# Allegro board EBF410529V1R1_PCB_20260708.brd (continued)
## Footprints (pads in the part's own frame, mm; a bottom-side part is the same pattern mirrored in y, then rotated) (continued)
USB-C-SMD_TYC-324G
  oval 1.5x1 hole 1.2x0.5: (-4.06,1.45) (4.06,1.45)
  round 0.5 hole 0.5 unplated: (-3.4,0.57) (3.4,0.57)
  oval 1x2.2 hole 0.6x1.6: 1(-4.32,1.93) 4(4.32,1.93)
  oval 1.2x2.4 hole 0.6x1.9: 2(-4.32,-2.62) 3(4.32,-2.62)
  rect 0.3x1 smd: A1(-2.62,2.62) A2(-2.13,2.62) A3(-1.63,2.62) A4(-1.13,2.62) A5(-0.62,2.62) A6(-0.12,2.62) A7(0.38,2.62) A8(0.88,2.62) A9(1.37,2.62) A10(1.87,2.62) A11(2.37,2.62) A12(2.88,2.62) B1(2.63,1.28) B2(2.13,1.28) B3(1.63,1.28) B4(1.13,1.28) B5(0.62,1.28) B6(0.12,1.28) B7(-0.38,1.28) B8(-0.87,1.28) B9(-1.37,1.28) B10(-1.87,1.28) B11(-2.37,1.28) B12(-2.88,1.28)
USON_10
  rect 0.2x0.7 smd: 1(-1,-0.45) 2(-0.5,-0.45) 4(0.5,-0.45) 5(1,-0.45) 6(1,0.45) 7(0.5,0.45) 9(-0.5,0.45) 10(-1,0.45)
  rect 0.4x0.7 smd: 3(0,-0.45) 8(0,0.45)
WQFN14-0R50-2R5X2R5EP1R45X1R45
  rect 0.6x0.3 smd: 1(-1.21,0.5) 2(-1.21,0) 3(-1.21,-0.5) 8(1.21,-0.5) 9(1.21,0) 10(1.21,0.5)
  rect 0.3x0.6 smd: 4(-0.75,-1.21) 5(-0.25,-1.21) 6(0.25,-1.21) 7(0.75,-1.21) 11(0.75,1.21) 12(0.25,1.21) 13(-0.25,1.21) 14(-0.75,1.21)
  rect 1.2x1.2 smd: 15(0,0)
ZH1P5MM_TH_2P
  round 1.05 hole 0.65: 1(-0.75,0) 2(0.75,0)

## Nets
3V3_OUT: C183.1 C185.1 J23.5 U31.1(OUT)
3V3_WLAN: C141.1 C142.1 Q11.3 U22.8
5V_OUT: C186.1 C187.1 J23.3 U32.1(OUT)
12V: C3.1 C4.1 C5.1 C6.1 C7.1 C12.1 C15.1 C162.1 C163.1 C180.1 F1.2 Q15.3 R8.2 R192.1 R219.1 R221.1 U1.3(VIN) U2.3(VIN) U26.3(VIN)
12V_OUT: C181.1 C182.1 J23.1 Q16.3
GND: C3.2 C4.2 C5.2 C6.2 C7.2 C8.2 C9.2 C12.2 C13.2 C14.2 C15.2 C16.2 C17.2 C18.2 C19.2 C20.2 C21.2 C22.2 C23.2 C24.2 C25.2 C26.2 C27.2 C28.2 C29.2 C30.2 C31.2 C32.2 C33.2 C34.2 C35.2 C36.2 C37.2 C38.2 C39.2 C40.2 C41.2 C42.2 C43.2 C44.2 C45.2 C46.2 C47.2 C48.2 C49.2 C50.2 C51.2 C52.2 C53.2 C54.2 C55.2 C56.2 C57.2 C58.2 C59.2 C60.2 C61.2 C62.2 C63.2 C64.2 C65.2 C66.2 C67.2 C68.2 C69.2 C70.2 C72.2 C73.2 C77.2 C78.2 C79.2 C80.2 C83.2 C84.2 C85.2 C87.1 C88.2 C90.2 C91.2 C92.2 C93.2 C94.2 C95.2 C96.2 C103.2 C104.2 C107.2 C108.2 C109.2 C110.2 C111.2 C112.2 C113.2 C114.2 C115.2 C116.2 C117.2 C118.2 C119.2 C120.2 C121.2 C122.2 C123.2 C124.2 C125.2 C126.2 C127.2 C128.2 C129.2 C130.2 C131.2 C132.2 C133.2 C134.2 C135.2 C136.2 C137.2 C138.2 C139.2 C141.2 C142.2 C144.2 C145.2 C146.2 C147.2 C148.2 C149.2 C150.2 C151.2 C152.2 C153.2 C154.2 C155.2 C156.2 C157.2 C158.2 C159.2 C160.2 C162.2 C163.2 C165.2 C166.2 C167.2 C168.2 C169.2 C172.2 C173.2 C174.2 C175.2 C176.2 C177.2 C181.2 C182.2 C183.2 C184.2 C185.2 C186.2 C187.2 C188.2 C189.2 C190.2 C191.2 C194.2 C195.2 C196.2 C197.2 C198.2 C199.2 C200.2 C201.2 C202.2 C203.2 C204.2 C205.2 C206.2 C207.2 C208.2 C209.2 C210.2 C212.1 C213.2 C214.2 C215.2 C226.2 CN1.2 CN1.3 D1.2 D2.1 D3.1 D4.1 D5.1 D6.1 D7.1 D8.1 D10.1 D11.1 D12.1 D13.1 D14.1 D15.1 D16.1 D17.1 D19.1 D20.1 D21.1 D22.1 D23.1 D24.1 D25.2 D26.1 D27.1 D28.1 D29.1 D30.2 D31.1 D32.2 D33.2 D34.1 D35.1 D37.1 D38.1 D39.1 D40.1 D43.1 D44.1 D45.1 D46.1 D47.2 D48.2 D49.1 D50.1 D51.1 D52.1 D53.1 D54.1 D55.1 D56.1 D57.2 D58.1 DN1.3 DN2.3 J1.2 J1.3 J2.2 J3.9 J3.10 J3.11 J3.12 J3.13 J3.14 J3.19 J3.20 J3.21 J3.22 J3.27 J3.28 J3.29 J3.30 J3.31 J3.32 J3.39 J3.44 J3.59 J3.60 J3.70 J3.73 J3.77 J3.92 J3.97 J3.108 J3.111 J3.115 J3.116 J3.127 J3.128 J3.143 J3.150 J3.161 J3.165 J3.166 J3.167 J3.177 J3.182 J3.191 J3.196 J3.197 J3.203 J3.210 J3.213 J3.217 J3.220 J3.230 J3.231 J3.236 J3.245 J3.250 J3.255 J3.260 J3.265 J3.270 J3.279 J3.284 J3.285 J3.299 J3.302 J3.305 J3.312 J3.314 J3.315 J3.316 J4.6(VSS) J4.10 J4.11 J4.12 J4.13 J5.2 J10.A1 J10.A12 J10.B1 J10.B12 J11.4 J11.7 J11.13 J11.16 J12.4 J12.10 J13.6 J13.7 J13.8 J13.16 J13.19 J13.22 J13.25 J13.28 J13.31 J13.32(SH2) J14.4 J14.18 J14.21 J14.23 J14.24 J14.25 J14.26(SH2) J15.4 J15.18 J15.21 J15.23 J15.24 J15.25 J15.26(SH2) J16.4 J16.18 J16.21 J16.23 J16.24 J16.25 J16.26(SH2) J17.4 J17.18 J17.21 J17.23 J17.24 J17.25 J17.26(SH2) J18.4 J18.18 J18.21 J18.23 J18.24 J18.25 J18.26(SH2) J19.5 J19.8 J19.9 J19.10 J19.11 J20.4 J20.9 J20.15 J20.18 J20.21 J20.26 J20.27 J20.29 J20.34 J20.35 J20.37 J20.40 J20.43 J20.50 J20.53 J20.54 J21.3 J23.2 J23.4 J23.6 J24.2 J24.5 J25.4 J26.4 J30.6 J32.6 J32.9 J32.14 J32.18 J33.2 J33.5 J33.8 J33.11 J33.17 L2.2 L10.2 L11.2 L12.2 L27.1 LED1.1(CATHODE) Q2.2(EMITTER) Q3.2(SOURCE) Q8.2(SOURCE) Q9.2(SOURCE) Q12.2(SOURCE) Q17.2(EMITTER) Q18.2(SOURCE) Q19.2(SOURCE) Q20.2(SOURCE) Q21.2(SOURCE) R2.2 R5.2 R7.2 R9.2 R14.2 R16.2 R38.2 R43.2 R44.2 R45.2 R50.2 R51.2 R54.2 R55.2 R56.2 R62.2 R65.2 R66.2 R69.2 R74.2 R75.2 R78.2 R79.2 R80.2 R85.1 R86.2 R90.2 R92.2 R94.2 R100.2 R101.2 R104.1 R120.2 R123.2 R124.2 R125.2 R133.2 R135.2 R137.1 R151.2 R154.2 R161.2 R165.2 R176.2 R178.2 R194.2 R196.2 R197.2 R212.2 R214.2 R217.2 R218.2 R226.2 R242.2 R243.2 SS5.1(NC_1) SS6.1(NC_1) SS7.1(NC_1) SS8.1(NC_1) SW1.1 SW1.3(GND1) SW2.1 SW2.3(GND1) SW3.1 SW3.3(GND1) U1.1 U2.1 U3.2 U4.1 U4.4 U5.4 U6.1 U7.41 U8.41 U9.4 U9.13 U9.18 U9.29 U10.7 U10.9 U11.8 U11.9 U11.15 U12.2 U13.2 U14.3 U14.8 U15.3 U15.8 U16.3 U16.8 U17.3 U17.8 U18.3 U18.8 U19.10 U19.24 U19.39 U20.2 U22.1 U22.5 U24.2 U25.2 U26.1 U27.2 U28.1(\\O\E) U28.3 U29.1(\\O\E) U29.3 U31.2 U32.2 U33.15 U34.2 U34.8 U35.2 U35.8 U36.5 U37.5 U38.7 U38.9 Y2.2 Y2.4(GND2) Y3.2 Y3.4(GND2) Y4.2 Y4.4(GND2)
VBUS5V0_TYPEC: C103.1 C104.1 J10.A4 J10.A9 J10.B4 J10.B9(VBUS4) U11.2 U12.1(OUT)
VCC3V3_RTC_S5: C31.1 D9.2 R241.1 U6.2(VOUT)
VCC5V0_SYS_S5: C11.2 C13.1 C14.1 C32.1 J3.1 J3.2 J3.3 J3.4 J3.5 J3.6 J3.7 J3.8 L3.2 R4.1 R6.2 R198.2 U6.3
VCC5V0_USB20_HOST: C111.1 C119.1 C128.1 C129.1 J11.10(VBUS) J12.1 J12.7(VBUS) U20.1(OUT)
VCC5V0_USB30_HOST: C107.1 C108.1 J11.1 U13.1(OUT)
VCC_1V8_S3: C133.1 C134.1 D58.2 J3.24 J3.25 J3.26 J30.1 R156.1 R158.1 R159.1
VCC_3V3_S0: C18.1 C19.1 C20.1 C21.1 J3.15 J3.16 J3.17 J3.18 J4.4 U3.5
VCC_RTC: C26.1 D9.3 R32.1 R157.1 U5.8
VCCA1V8_PLDO2_S0: J3.23 R15.1
VDD_3V3: C16.1 C17.1 C33.1 C34.1 C35.1 C49.1 C50.1 C51.1 C91.1 C92.1 C143.1 C176.1 C177.1 C189.1 C196.1 J32.1 J32.17 L5.1 L7.1 L8.1 L9.1 L15.2 L16.1 L17.1 Q6.1 Q7.1 Q11.2(SOURCE) R3.1 R12.1 R21.1 R22.1 R33.1 R34.1 R35.1 R46.1 R47.1 R48.1 R53.1 R57.1 R58.1 R59.1 R70.1 R71.1 R72.1 R77.1 R82.2 R87.1 R91.1 R97.2 R103.1 R109.1 R127.1 R136.1 R139.1 R141.1 R142.1 R144.1 R145.1 R146.1 R148.1 R150.1 R160.1 R162.1 R163.1 R188.1 R189.1 R190.1 R235.1 R236.1 R237.1 R238.1 R239.1 R240.1 U3.1(OUT) U7.28 U7.29 U8.28 U8.29 U11.3 U11.4(VDD2) U11.12 U11.13 U25.5 U28.5 U29.5 U31.5 U34.5(VIO) U35.5(VIO)
VDD_5V: C2.2 C8.1 C9.1 C93.1 C94.1 C151.1 C152.1 C153.1 C154.1 C155.1 C156.1 C157.1 C158.1 C159.1 C160.1 C190.1 C197.1 D36.2 J32.2 J32.4 L1.2 Q1.2(SOURCE) Q10.1 R1.2 R10.1 R126.1 R140.1 R147.1 R166.1 R167.1 R168.1 R169.1 R170.1 R220.1 R222.1 U12.5 U13.5 U20.5 U24.5 U32.5 U34.3 U35.3
BAT_RTC: C24.1 D9.1 D10.2 J5.1
BM8563_INT: D18.1 Q3.1 R32.2 R157.2 U5.3(\\I\N\T)
BOOT_SARADC_IN0: J3.94 R27.2
CAM0_PWDN: J3.86 J14.15
CAM0_RSTN: J3.84 J14.22
CAM1_PWDN: J3.78 J15.15
CAM1_RSTN: J3.76 J15.22
CAM2_PWDN: J3.80 J16.15
CAM2_RSTN: J3.82 J16.22
CAM3_PWDN: J3.72 J18.15
CAM3_RSTN: J3.74 J18.22
CAM4_PWDN: J3.88 J17.15
CAM4_RSTN: J3.90 J17.22
CAN0_H: D57.1 J29.1 R205.1 U34.7
CAN0_L: D47.1 J29.2 R205.2 U34.6
CAN0_RX_M2: J3.50 U34.4
CAN0_TX_M2: J3.48 U34.1
CAN1_H: D30.1 J29.3 R206.1 U35.7
CAN1_L: D25.1 J29.4 R206.2 U35.6
CAN1_RX_M3: J3.151 U35.4
CAN1_TX_M3: J3.149 U35.1
CTP_INT: J3.175 J13.11 R144.2
CTP_RST: J3.173 J13.12 R145.2
DP_TX_AUXN: C106.2 J3.295
DP_TX_AUXP: C105.2 J3.297
DSI_VDD3V3: C145.1 C146.1 J13.4 J13.5 U25.1(OUT)
DSI_VDD5V: C138.1 C139.1 J13.1 J13.2 J13.3 U24.1(OUT)
EARPHONE_CTL: J3.129 R95.2
ETH0_MCLK_M0: J3.75 R49.1
ETH0_MDC_M0: J3.41 R48.2 U7.13
ETH0_MDIO_M0: J3.43 R47.2 U7.14
ETH0_RSTN: D59.1 J3.45
ETH0_RXCLK_M0: J3.71 R41.1 R44.1
ETH0_RXCTL_M0: J3.67 R42.1 R45.1
ETH0_RXD0_M0: J3.63 R33.2 R37.1
ETH0_RXD1_M0: J3.69 R34.2 R36.1
ETH0_RXD2_M0: J3.61 R39.1 R43.1
ETH0_RXD3_M0: J3.65 R35.2 R40.1
ETH0_TXCLK_M0: J3.47 U7.20
ETH0_TXCTL_M0: J3.53 U7.19
ETH0_TXD0_M0: J3.57 U7.18
ETH0_TXD1_M0: J3.51 U7.17
ETH0_TXD2_M0: J3.55 U7.16
ETH0_TXD3_M0: J3.49 U7.15
ETH1_MCLK_M0: J3.113 R73.1
ETH1_MDC_M0: J3.83 R72.2 U8.13
ETH1_MDIO_M0: J3.81 R71.2 U8.14
ETH1_RSTN: D60.1 J3.79
ETH1_RXCLK_M0: J3.109 R59.2 R67.1
ETH1_RXCTL_M0: J3.103 R68.1 R69.1
ETH1_RXD0_M0: J3.99 R57.2 R60.1
ETH1_RXD1_M0: J3.105 R58.2 R61.1
ETH1_RXD2_M0: J3.101 R63.1 R65.1
ETH1_RXD3_M0: J3.107 R64.1 R66.1
ETH1_TXCLK_M0: J3.89 U8.20
ETH1_TXCTL_M0: J3.93 U8.19
ETH1_TXD0_M0: J3.87 U8.18
ETH1_TXD1_M0: J3.95 U8.17
ETH1_TXD2_M0: J3.85 U8.16
ETH1_TXD3_M0: J3.91 U8.15
FAN_CTRL: J3.46 R13.1
FUSB302_INT: J3.232 R109.2 U11.5
HDMI_5V: C226.1 D36.1 D48.1 J33.18
HDMI_TX_CEC_M0: J3.117 R152.1
HDMI_TX_CEC_PORT: D43.2 J33.13 Q10.3
HDMI_TX_D0N: C221.1 J3.248
HDMI_TX_D0N_PORT: C221.2 D50.2 J33.9 R233.1
HDMI_TX_D0P: C220.1 J3.246
HDMI_TX_D0P_PORT: C220.2 D49.2 J33.7 R234.1
HDMI_TX_D1N: C219.1 J3.244
HDMI_TX_D1N_PORT: C219.2 D56.2 J33.6 R231.1
HDMI_TX_D1P: C218.1 J3.242
HDMI_TX_D1P_PORT: C218.2 D55.2 J33.4 R232.1
HDMI_TX_D2N: C217.1 J3.240
HDMI_TX_D2N_PORT: C217.2 D54.2 J33.3 R229.1
HDMI_TX_D2P: C216.1 J3.238
HDMI_TX_D2P_PORT: C216.2 D53.2 J33.1 R230.1
HDMI_TX_D3N: C223.1 J3.254
HDMI_TX_D3N_PORT: C223.2 D52.2 J33.12 R227.1
HDMI_TX_D3P: C222.1 J3.252
HDMI_TX_D3P_PORT: C222.2 D51.2 J33.10 R228.1
HDMI_TX_EARC+: C224.2 D44.2 J33.14
HDMI_TX_EARC-: C225.2 D31.2 J33.19 R149.2
HDMI_TX_HPDIN_M0: J3.125 Q8.3 R141.2
HDMI_TX_ON_H: J3.123 R164.1
HDMI_TX_SBDN: C225.1 J3.258
HDMI_TX_SBDP: C224.1 J3.256
HDMI_TX_SCL: J3.121 Q6.2(SOURCE) R139.2
HDMI_TX_SCL_PORT: D45.2 J33.15 Q6.3 R140.2
HDMI_TX_SDA: J3.119 Q7.2(SOURCE) R146.2
HDMI_TX_SDA_PORT: D46.2 J33.16 Q7.3 R147.2
HP_BUTTON_DET: C77.1 J3.106 R83.2 R86.1
HP_PLUG_IN_DET: J3.131 R88.2
I2C2_SCL_M0: J3.134 J13.9 R239.2 U11.6
I2C2_SDA_M0: J3.136 J13.10 R240.2 U11.7
I2C3_SCL_M0: J3.62 J14.6 R162.2 U5.6 U9.28
I2C3_SDA_M0: J3.64 J14.5 R160.2 U5.5 U9.27
I2C4_SCL_M2: J3.148 J15.6 R188.2
I2C4_SDA_M2: J3.146 J15.5 R163.2
I2C5_SCL_M3: J3.130 J16.6 R190.2
I2C5_SDA_M3: J3.132 J16.5 R189.2
I2C7_SCL_M1: J3.66 J18.6 J32.5 R236.2
I2C7_SDA_M1: J3.68 J18.5 J32.3 R235.2
I2C8_SCL_M2: J3.144 J17.6 R238.2
I2C8_SDA_M2: J3.142 J17.5 R237.2
LCD_BL_PWM: J3.169 J13.13
LCD_PWR_EN: J3.228 R153.1
LCD_RST: J3.171 J13.15
LOUT1: C81.2 U9.12
LOUT2: C86.1 U9.15
MASKROM: C25.1 D11.2 R27.1 SW1.2
MIC1N: C74.2 R85.2
MIC1P: C71.2 R81.2
MIC2N: C76.2 C89.2 P1.2 R101.1
MIC2P: C75.2 C89.1 P1.1(OUT) R99.2
MINIPCIE_3V3: C135.1 C164.2 C165.1 C166.1 C172.1 C173.1 C174.1 C175.1 J20.2 J20.24 J20.39 J20.41 J20.52 L14.2 R172.2 R179.1
MINIPCIE_NWDISABLE: J3.133 R182.2
MINIPCIE_PWR_EN: J3.135 R177.1
MIPI_DPHY_CSI0_RX_CLKN: J3.269 J14.10
MIPI_DPHY_CSI0_RX_CLKP: J3.267 J14.9
MIPI_DPHY_CSI0_RX_D0N: J3.277 J14.12
MIPI_DPHY_CSI0_RX_D0P: J3.275 J14.11
MIPI_DPHY_CSI0_RX_D1N: J3.273 J14.8
MIPI_DPHY_CSI0_RX_D1P: J3.271 J14.7
MIPI_DPHY_CSI0_RX_D2N: J3.263 J14.17
MIPI_DPHY_CSI0_RX_D2P: J3.261 J14.16
MIPI_DPHY_CSI0_RX_D3N: J3.259 J14.20
MIPI_DPHY_CSI0_RX_D3P: J3.257 J14.19
MIPI_DPHY_CSI1_RX_CLKN: J3.221 J15.10
MIPI_DPHY_CSI1_RX_CLKP: J3.219 J15.9
MIPI_DPHY_CSI1_RX_D0N: J3.225 J15.12
MIPI_DPHY_CSI1_RX_D0P: J3.223 J15.11
MIPI_DPHY_CSI1_RX_D1N: J3.229 J15.8
MIPI_DPHY_CSI1_RX_D1P: J3.227 J15.7
MIPI_DPHY_CSI2_RX_CLKN: J3.241 J16.10
MIPI_DPHY_CSI2_RX_CLKP: J3.243 J16.9
MIPI_DPHY_CSI2_RX_D0N: J3.233 J16.12
MIPI_DPHY_CSI2_RX_D0P: J3.235 J16.11
MIPI_DPHY_CSI2_RX_D1N: J3.237 J16.8
MIPI_DPHY_CSI2_RX_D1P: J3.239 J16.7
MIPI_DPHY_CSI3_RX_CLKN: J3.194 J18.10
MIPI_DPHY_CSI3_RX_CLKP: J3.192 J18.9
MIPI_DPHY_CSI3_RX_D0N: J3.186 J18.12
MIPI_DPHY_CSI3_RX_D0P: J3.184 J18.11
MIPI_DPHY_CSI3_RX_D1N: J3.190 J18.8
MIPI_DPHY_CSI3_RX_D1P: J3.188 J18.7
MIPI_DPHY_CSI4_RX_CLKN: J3.208 J17.10
MIPI_DPHY_CSI4_RX_CLKP: J3.206 J17.9
MIPI_DPHY_CSI4_RX_D0N: J3.200 J17.12
MIPI_DPHY_CSI4_RX_D0P: J3.198 J17.11
MIPI_DPHY_CSI4_RX_D1N: J3.204 J17.8
MIPI_DPHY_CSI4_RX_D1P: J3.202 J17.7
MIPI_DPHY_DSI_TX_CLKN: J3.274 J13.24
MIPI_DPHY_DSI_TX_CLKP: J3.272 J13.23
MIPI_DPHY_DSI_TX_D0N: J3.282 J13.27
MIPI_DPHY_DSI_TX_D0P: J3.280 J13.26
MIPI_DPHY_DSI_TX_D1N: J3.278 J13.21
MIPI_DPHY_DSI_TX_D1P: J3.276 J13.20
MIPI_DPHY_DSI_TX_D2N: J3.268 J13.18
MIPI_DPHY_DSI_TX_D2P: J3.266 J13.17
MIPI_DPHY_DSI_TX_D3N: J3.264 J13.30
MIPI_DPHY_DSI_TX_D3P: J3.262 J13.29
ON/OFF: C30.1 D13.2 R31.1 SW3.2
PCIE0_CLKREQN_M0: J3.139 R181.1
PCIE0_PERSTN: J3.141 R183.2
PCIE0_REFCLKN: J3.199 J20.11
PCIE0_REFCLKP: J3.201 J20.13
PCIE0_RXN: J3.209 J20.23
PCIE0_RXP: J3.211 J20.25
PCIE0_TXN: C170.1 J3.205
PCIE0_TXP: C171.1 J3.207
PCIE0_WAKEN_M0: J3.137 R180.1
PE_TXN: C170.2 J20.31
PE_TXP: C171.2 J20.33
PMIC_EXT_EN: J3.37 R199.1
PWM0_CH0_M0_IR: J3.215 R21.2 R26.1
PWM2_CH3_M3: J3.122 J32.11
PWM2_CH6_M3: J3.124 J32.10
PWM2_CH7_M3: J3.126 J32.8
PWR_3V3_EN: J3.112 R195.1
PWR_5V_EN: J3.110 R200.1
PWR_12V_EN: J3.114 R193.1
PWR_ON: J3.33 Q12.3 R31.2
RECOVERY: C27.1 D12.2 R30.1 SW2.2
RECOVERY_KEY: J3.96 R30.2
RK806_VDC: J3.35 R198.1
RMII0_AVDD33: C46.1 C47.1 C48.1 L5.2 R52.2 U7.11 U7.40
RMII0_LED1: C150.1 J6.14 R56.1 U7.33
RMII0_LED2: C149.1 J6.11 R54.1 U7.34
RMII0_MDIN0: J6.3 U7.2
RMII0_MDIN1: J6.7 U7.5
RMII0_MDIN2: J6.6 U7.7
RMII0_MDIN3: J6.9 U7.10
RMII0_MDIP0: J6.2 U7.1
RMII0_MDIP1: J6.4 U7.4
RMII0_MDIP2: J6.5 U7.6
RMII0_MDIP3: J6.8 U7.9
RMII0_VDD10: C36.1 C37.1 C38.1 C39.1 C40.1 L4.2 U7.3 U7.8 U7.21 U7.38
RMII1_AVDD33: C62.1 C63.1 C64.1 L7.2 R76.2 U8.11 U8.40
RMII1_LED1: C147.1 J7.14 R80.1 U8.33
RMII1_LED2: C144.1 J7.11 R79.1 U8.34
RMII1_MDIN0: J7.3 U8.2
RMII1_MDIN1: J7.7 U8.5
RMII1_MDIN2: J7.6 U8.7
RMII1_MDIN3: J7.9 U8.10
RMII1_MDIP0: J7.2 U8.1
RMII1_MDIP1: J7.4 U8.4
RMII1_MDIP2: J7.5 U8.6
RMII1_MDIP3: J7.8 U8.9
RMII1_VDD10: C52.1 C53.1 C54.1 C55.1 C56.1 L6.2 U8.3 U8.8 U8.21 U8.38
ROUT1: C82.2 U9.11
ROUT2: C211.1 U9.14
RS232_R1IN: J24.4 U33.13
RS232_R1OUT: J27.1 U33.12
RS232_R2IN: J24.1 U33.8
RS232_R2OUT: J28.1 U33.9
RS232_T1IN: J27.2 U33.11
RS232_T1OUT: J24.6 U33.14
RS232_T2IN: J28.2 U33.10
RS232_T2OUT: J24.3 U33.7
RS485_1_3V3: C198.1 D41.2 L16.2 U36.8(VCC)
RS485_1_A: DN1.2(C2) J31.2 R211.2 R213.1 U36.6
RS485_1_B: DN1.1 J31.1 R211.1 R214.1 U36.7
RS485_1_DIR: J3.180 R212.1 U36.2 U36.3
RS485_2_3V3: C199.1 D42.2 L17.2 U37.8(VCC)
RS485_2_A: DN2.2(C2) J31.4 R215.1 R216.2 U37.6
RS485_2_B: DN2.1 J31.3 R216.1 R218.1 U37.7
RS485_2_DIR: J3.178 R217.1 U37.2 U37.3
RTC_INT: D18.2 J3.222 R156.2
SAI1_LRCK_M0: J3.36 U9.7
SAI1_MCLK_M0: J3.34 U9.1
SAI1_SCLK_M0: J3.38 U9.5
SAI1_SDI0_M0: J3.42 U9.8
SAI1_SDO2_M0: J3.40 U9.6
SARADC_IN3: J3.104 R15.2 R16.1 R207.1
SARADC_IN5: J3.102 R208.1
SARADC_IN6: J3.100 R209.1
SARADC_IN7: J3.98 R210.1
SDMMC0_CLK: J3.164 R20.1
SDMMC0_CMD: J3.158 R19.1
SDMMC0_D0: J3.160 R23.1
SDMMC0_D1: J3.162 R24.1
SDMMC0_D2: J3.154 R17.1
SDMMC0_D3: J3.156 R18.1
SDMMC0_DETN: J3.152 R25.1
SIM_CLK0: J20.12 R174.1
SIM_DATA0: J20.10 R175.1
SIM_RST0: J20.14 R173.1
SIM_VDD: J19.1 J20.8 R171.1 U27.1
SPI1_CLK_M0: J3.174 J32.12
SPI1_CSN1_M0: J3.168 J32.16
SPI1_MISO_M0: J3.172 J32.15
SPI1_MOSI_M0: J3.176 J32.13
SPK_CTRL: J3.120 R102.1 R225.1
SPK_LN: C205.1 J9.1 L18.2
SPK_LP: C90.1 J9.2 L19.2
SPK_RN: C214.1 J22.1 L20.2
SPK_RP: C213.1 J22.2 L21.2
SUB1: C105.1 D23.2 J10.A8 R119.1 R123.1
SUB2: C106.1 D24.2 J10.B8 R122.1 R124.1
SYS_LED: J3.118 LED2.1(CATHODE)
TYPEC_CC1: C96.1 D21.2 J10.A5 U11.10 U11.11
TYPEC_CC2: C95.1 D22.2 J10.B5 U11.1 U11.14
TYPEC_DM: D20.2 J10.A7 J10.B7 R108.1
TYPEC_DP: D19.2 J10.A6 J10.B6 R107.1
TYPEC_DPTX_AUX_PUPDCTL1: J3.283 R119.2
TYPEC_DPTX_AUX_PUPDCTL2: J3.281 R122.2
TYPEC_SSRXN1: J10.B10 R113.1 U16.5 U16.6(NC4)
TYPEC_SSRXN2: J10.A10 R117.1 U14.5 U14.6(NC4)
TYPEC_SSRXP1: J10.B11 R112.1 U16.4 U16.7
TYPEC_SSRXP2: J10.A11 R114.1 U14.4 U14.7
TYPEC_SSTXN1: C100.1 J10.A3 U16.1 U16.10
TYPEC_SSTXN2: C102.1 J10.B3 U14.1 U14.10
TYPEC_SSTXP1: C99.1 J10.A2 U16.2 U16.9
TYPEC_SSTXP2: C101.1 J10.B2 U14.2 U14.9
TYPEC_VBUS_EN: J3.234 R118.1
U8_RX: J25.3 J27.5
U8_TX: J25.2 J27.6
U10_RX: J26.3 J28.5
U10_TX: J26.2 J28.6
UART0_RX: R187.2 U29.2
UART0_RX_M0_DEBUG: J3.159 U29.4
UART0_TX: R186.2 U28.4
UART0_TX_M0_DEBUG: J3.157 U28.2
UART3_RX_M1: J3.52 U36.1
UART3_TX_M1: J3.54 U36.4
UART5_RX_M0: J3.58 U37.1
UART5_TX_M0: J3.56 U37.4
UART8_RX: D38.2 J27.3 R203.2
UART8_RX_M2: J3.145 R203.1
UART8_TX: D37.2 J27.4 R204.2
UART8_TX_M2: J3.147 R204.1
UART10_RX: D40.2 J28.3 R201.2
UART10_RX_M1: J3.153 R201.1
UART10_TX: D39.2 J28.4 R202.2
UART10_TX_M1: J3.155 R202.1
USB2_OTG0_DM: J3.291 R108.2
USB2_OTG0_DP: J3.293 R107.2
USB2_OTG0_ID: J3.247 R104.2
USB2_OTG0_VBUSDET: J3.249 R103.2
USB2_OTG1_DM: J3.287 R132.1
USB2_OTG1_DP: J3.289 R131.1
USB2_OTG1_ID: J3.251 R137.2
USB2_OTG1_VBUSDET: J3.253 R136.2
USB3_OTG0_SSRX1N: J3.300 R113.2
USB3_OTG0_SSRX1P: J3.298 R112.2
USB3_OTG0_SSRX2N: J3.292 R117.2
USB3_OTG0_SSRX2P: J3.290 R114.2
USB3_OTG0_SSTX1N: C100.2 J3.294
USB3_OTG0_SSTX1P: C99.2 J3.296
USB3_OTG0_SSTX2N: C102.2 J3.286
USB3_OTG0_SSTX2P: C101.2 J3.288
USB3_OTG1_SSRXN: J3.212 R110.2
USB3_OTG1_SSRXP: J3.214 R111.2
USB3_OTG1_SSTXN: C97.2 J3.216
USB3_OTG1_SSTXP: C98.2 J3.218
USB20_DM2: J11.11 R115.1 U15.2 U15.9
USB20_DP2: J11.12 R116.1 U15.1 U15.10
USB20_HOST_PWR_EN: J3.224 R134.1
USB30_DM: J11.2 R105.1 U17.5 U17.6(NC4)
USB30_DP: J11.3 R106.1 U17.4 U17.7
USB30_HOST_PWR_EN: J3.226 R121.1
USB30_RXN: J11.5 R110.1 U17.1 U17.10
USB30_RXP: J11.6 R111.1 U17.2 U17.9
USB30_TXN: C97.1 J11.8 U15.4 U15.7
USB30_TXP: C98.1 J11.9 U15.5 U15.6(NC4)
USB_HUB_1V8: C123.1 C124.1 C125.1 C126.1 C127.1 U19.6 U19.21 U19.25 U19.28
USB_HUB_3V3: C109.1 C110.1 C116.1 C117.1 C118.1 C120.1 C121.1 R127.2 R128.2 R129.2 R130.2 U19.15 U19.20 U19.26 U19.31 U19.36 U19.42 U19.43 U19.45
USB_HUB_3V3_OUT: C114.1 C115.1 R128.1 U19.9
USB_HUB_5V0: C112.1 C113.1 R126.2 U19.8
USB_HUB_DM1: R105.2 U19.18
USB_HUB_DM2: R115.2 U19.16
USB_HUB_DM3: J12.2 U18.2 U18.9 U19.13
USB_HUB_DM4: J12.8 U18.5 U18.6(NC4) U19.11
USB_HUB_DM5: D33.1 R184.2 U19.32
USB_HUB_DM6: R143.1 U19.34
USB_HUB_DP1: R106.2 U19.19
USB_HUB_DP2: R116.2 U19.17
USB_HUB_DP3: J12.3 U18.1 U18.10 U19.14
USB_HUB_DP4: J12.9 U18.4 U18.7 U19.12
USB_HUB_DP5: D32.1 R185.2 U19.33
USB_HUB_DP6: R138.1 U19.35
WIFI_PWR_EN: J3.170 R155.1
N16958730: J1.1 J1.5 L2.1
N16958788: F1.1 J1.4
N16959452: R3.2 U1.5
N16959455: C1.2 L1.1 U1.2
N16959497: C1.1 U1.6
N16959529: C2.1 R1.1 R2.1 U1.4
N16961161: C10.2 L3.1 U2.2
N16961195: C11.1 R6.1 R7.1 U2.4
N16961199: C10.1 U2.6
N16961300: R8.1 R9.1 U2.5
N16963036: LED1.2 R4.2
N16963423: LED2.2 R12.2
N16965184: D8.2 J4.1 R17.2
N16965201: D7.2 J4.2 R18.2
N16965205: D6.2 J4.3 R19.2
N16965209: D5.2 J4.5 R20.2
N16965213: D4.2 J4.7 R23.2
N16965217: D3.2 J4.8 R24.2
N16965221: D2.2 J4.9 R25.2
N16966392: R26.2 U4.3
N16966399: C22.1 C23.1 R22.2 U4.2(VCC)
N16970771: R39.2 U7.23
N16970773: R36.2 U7.24
N16970775: R37.2 U7.25
N16970777: R42.2 U7.26
N16970779: R41.2 U7.27
N16970781: R40.2 U7.22
N16970797: R49.2 U7.35
N16970858: C42.1 U7.36 Y2.3
N16970862: C41.1 U7.37(XTAL_OUT) Y2.1
N16970890: C45.1 D59.2 R53.2 R158.2 U7.12
N16971097: R38.1 U7.39
N16971189: L4.1 U7.30
N16971238: C43.1 J6.1
N16971259: C44.1 J6.10 J6.15 J6.16 R55.1
N16971318: J6.12 R50.1
N16971320: J6.13(YELC) R51.1
N16971466: R52.1 U7.32
N16971541: R46.2 U7.31
N16976499: R68.2 U8.26
N16976501: R60.2 U8.25
N16976503: R61.2 U8.24
N16976505: R63.2 U8.23
N16976507: R64.2 U8.22
N16976509: R67.2 U8.27
N16976515: R73.2 U8.35
N16976541: C57.1 U8.37(XTAL_OUT) Y3.1
N16976545: C58.1 U8.36 Y3.3
N16976569: C61.1 D60.2 R77.2 R159.2 U8.12
N16976627: R62.1 U8.39
N16976649: L6.1 U8.30
N16976697: R76.1 U8.32
N16976807: C59.1 J7.1
N16976809: C60.1 J7.10 J7.15 J7.16 R78.1
N16976831: J7.13(YELC) R75.1
N16976833: J7.12 R74.1
N16976861: R70.2 U8.31
N16985416: J10.1 J10.2 J10.3 J10.4 L11.1
N16990092: R120.1 U12.3
N16998300: Q10.2(SOURCE) R150.2 R152.2
N17003573: Q18.1 Q19.1 Q20.1 Q21.1 R164.2 R165.1
N17013167: Q8.1 Q9.3 R142.2
N17014356: Q9.1 R149.1 R151.1
N17018699: J15.1 J15.2 J15.3 R167.2
N17022868: J16.1 J16.2 J16.3 R168.2
N17023671: J18.1 J18.2 J18.3 R170.2
N17024139: J17.1 J17.2 J17.3 R169.2
N17026345: J14.1 J14.2 J14.3 R166.2
N17029455: C148.1 R153.2 U24.4 U25.4
N17029502: R154.1 U24.3
N17029521: R161.1 U25.3
N17036087: C169.1 J19.2 R173.2 U27.6
N17036090: C168.1 J19.3 R174.2 U27.4
N17036093: C167.1 J19.7 R171.2 R175.2 U27.5
N17043477: C161.2 L14.1 U26.2
N17043505: C161.1 U26.6
N17043507: C164.1 R172.1 R176.1 U26.4
N17043614: R177.2 R178.1 U26.5
N17043933: J20.1 R179.2 R180.2
N17044212: J20.7 R181.2
N17046085: J20.38 R185.1
N17046088: J20.36 R184.1
N17046548: J20.20 R182.1
N17046561: J20.22 R183.1
N17063858: C66.1 C67.1 C68.1 C69.1 L8.2 U9.16 U9.17
N17063899: C72.1 C73.1 L9.2 U9.2 U9.3
N17064255: C71.1 U9.24
N17064258: C74.1 U9.23
N17064495: C75.1 U9.22
N17064497: C76.1 U9.21
N17064707: C78.1 U9.20
N17064710: C79.1 U9.19
N17064713: C80.1 U9.10(VREF)
N17064960: R91.2 U9.26
N17065329: C85.1 R97.1 R99.1
N17072089: C65.1 D14.2 J8.1 R81.1 R83.1 R84.2
N17072509: C70.1 R82.1 R84.1
N17073944: J8.2 R92.1
N17074279: C83.1 D15.2 J8.6 R87.2 R88.1
N17074336: D17.2 J8.3 Q5.2(SOURCE) R243.1
N17074726: D16.2 J8.4 Q4.2(SOURCE) R242.1
N17074747: Q4.3 R89.1 R90.1
N17075125: C81.1 R89.2
N17075408: Q5.3 R93.1 R94.1
N17075443: C82.1 R93.2
N17075521: C84.1 Q4.1 Q5.1 R95.1
N17112236: C29.1 U5.2 Y1.2
N17112246: C28.1 U5.1 Y1.1
N17117541: R118.2 U12.4
N17135429: R5.1 U3.3
N17149641: R121.2 U13.4
N17149662: R125.1 U13.3
N17150434: J11.19 J11.20 J11.21 J11.22 L10.1
N17156781: R133.1 U19.27
N17157129: C131.1 U19.22 Y4.3
N17157136: C130.1 U19.23 Y4.1
N17158781: C122.1 R130.1 U19.41
N17159812: R129.1 U19.40
N17161099: R131.2 U19.30
N17161102: R132.2 U19.29
N17163205: J12.5 J12.6 J12.11 J12.12 L12.1
N17166688: C132.1 R134.2 U20.4
N17166697: R135.1 U20.3
N17204481: D34.2 J21.2 R187.1
N17204515: D35.2 J21.1 R186.1
N17208013: Q1.3 R11.1
N17208331: D1.1(K) J2.1 R11.2
N17208813: Q1.1 Q2.3 R10.2
N17208925: Q2.1 R13.2 R14.1
N17240897: C180.2 Q15.1 Q16.1 Q17.3 R192.2
N17241015: Q15.2(SOURCE) R191.1
N17241092: Q16.2(SOURCE) R191.2
N17241660: Q17.1 R193.2 R194.1
N17241919: C184.1 R195.2 U31.4
N17241951: R196.1 U31.3
N17242291: C188.1 R200.2 U32.4
N17242323: R197.1 U32.3
N17257942: R199.2 U3.4
N17272255: C191.1 L15.1 U33.16(VCC)
N17272410: C192.1 U33.3
N17272413: C192.2 U33.1
N17272453: C193.2 U33.4
N17272456: C193.1 U33.5
N17272490: C194.1 U33.6
N17272493: C195.1 U33.2
N17276502: D29.2 J30.2 R207.2
N17276503: D28.2 J30.3 R208.2
N17276504: D27.2 J30.4 R209.2
N17276505: D26.2 J30.5 R210.2
N17284003: D41.1 R213.2
N17284390: D42.1 R215.2
N17313600: C200.1 C201.1 C202.1 C203.1 C204.1 R219.2 R220.2 U38.6
N17313897: R96.2 U38.4
N17313900: R98.2 U38.3
N17314015: C87.2 R98.1
N17314022: C86.2 R96.1
N17314158: R100.1 R102.2 U38.1
N17314600: C88.1 U38.2
N17314610: L18.1 U38.5
N17314613: L19.1 U38.8(VOP)
N17315365: C206.1 C207.1 C208.1 C209.1 C210.1 R221.2 R222.2 U10.6
N17315397: R224.2 U10.3
N17315399: R223.2 U10.4
N17315425: C212.2 R224.1
N17315432: C211.2 R223.1
N17315446: R225.2 R226.1 U10.1
N17315502: C215.1 U10.2
N17315506: L21.1 U10.8(VOP)
N17315508: L20.1 U10.5
N17318769: J33.G1 J33.G2 J33.G3 J33.G4 L27.2
N17319613: Q21.3 R233.2 R234.2
N17319615: Q20.3 R231.2 R232.2
N17319817: Q19.3 R229.2 R230.2
N17319825: Q18.3 R227.2 R228.2
N17366542: C136.1 C140.1 U22.2
N17366552: C137.1 C140.2 CN1.1
N17367118: R138.2 U22.6
N17367190: R143.2 U22.7
N17367932: C143.2 Q11.1 R148.2 R155.2
N17525748: Q3.3 Q12.1 R241.2

Pads without a net: J3 138 140 163 179 181 183 185 187 189 193 195 301 303 304 306 307 308 309 310 311 313; J8 7 8; J11 14 15 17 18; J13 14; J14 13 14; J15 13 14 16 17 19 20; J16 13 14 16 17 19 20; J17 13 14 16 17 19 20; J18 13 14 16 17 19 20; J19 4 6; J20 3 5 6 16 17 19 28 30 32 42 44 45 46 47 48 49 51; J25 1; J26 1; J32 7; U5 7; U9 9 25; U19 1 2 3 4 5 7 37 38 44 46 47 48; U22 3 4 9 10 11 12 13 14; U27 3

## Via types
v1: diameter 0.406, hole 0.203, TOP to BOTTOM, 2027 vias
v2: diameter 0.61, hole 0.305, TOP to BOTTOM, 53 vias

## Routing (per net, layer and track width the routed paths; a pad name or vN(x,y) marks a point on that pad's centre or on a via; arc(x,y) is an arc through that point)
3V3_OUT: length 15.8
  TOP w0.508: C185.1 60.84,10.3 62.94,8.2 69.09,8.2 70.77,6.52 J23.5
3V3_WLAN: length 5.3
  TOP w0.508: Q11.3 122.46,39.09 C141.1 C142.1 U22.8
5V_OUT: length 14.4
  TOP w0.508: C186.1 65.67,10.86 66.24,10.29 70.54,10.29 74.77,6.05 J23.3
12V: length 2.8
  TOP w0.254: C180.1 v1(69.99,12.83) R192.1 ; Q15.3 v1(76.11,13.64)
  vias: v1(40.82,67.69) v1(41.62,67.69) v1(77.11,13.64) v1(77.11,12.64) v1(112.03,34.75) v1(112.03,33.66) v1(112.03,32.56) v1(113.03,34.75) v1(113.03,32.56) v2(9.3,69.22) v2(10.3,69.22) v2(10.3,68.22) v2(11.3,69.22) v2(11.3,68.22) v2(14.18,69.22) v2(14.18,68.22)
12V_OUT: length 15.1
  TOP w0.508: J23.1 78.77,5.25 77.86,6.16 C182.1 77.86,13.22 78.36,13.72 C181.1 76.62,14.86 76.11,15.37 Q16.3
GND: length 1558.3
  TOP w0.152: R137.1 79.5,50.2 79.5,54.37 v1(79.44,54.43) ; J10.B12 30.81,84.98 30.64,85.16 v1(30.64,85.47)
  TOP w0.203: 96.42,51.84 96.82,52.25 96.42,52.65 v1(96.42,54.53)
  TOP w0.254: U28.3 v1(7.38,74.78) 7.75,75.15 D35.1 ; C174.2 v1(136.65,23.76) ; v1(8.33,72.87) U28.1 7.38,71.88 ; C22.2 135.9,6.67 136.41,6.16 v1(136.94,6.16) U4.1 ; C154.2 v1(9.91,33.21) ; v1(96.18,46.6) 96.6,46.6 Y4.4 ; v1(96.18,46.6) v1(96.18,45.85) v1(97.2,45.85) v1(98.2,45.85) v1(99.2,45.85) v1(100.2,45.85) C130.2 ; v1(96.18,46.6) v1(96.18,47.6) 96.17,47.6 v1(96.17,48.6) 96.16,48.6 v1(96.16,49.6) 96.18,49.6 v1(96.18,50.6) v1(97.2,50.6) v1(98.2,50.6) ; D43.1 86.96,69.2 v1(86.86,69.1) ; C45.2 60.73,33.4 v1(60.55,33.22) ; v1(105.46,54.81) 105.79,54.81 Q9.2 ; v1(130.82,20.06) J20.34 v1(130.82,17.32) ; 73.86,41.25 72.06,41.25 71.32,41.99 ; v1(70.99,33.99) v1(71.99,33.99) v1(72.99,33.99) v1(73.99,33.99) v1(74.99,33.99) v1(74.99,32.99) ; v1(70.99,33.99) 70.99,33.22 C41.2 ; v1(70.99,33.99) R38.2 70.33,33.99 ; v1(24.44,57.25) 24.25,57.25 23.94,56.94 J3.39 ; J3.128 v1(46.19,61.44) ; v1(73.63,65.23) 73.69,65.17 J3.230 ; R69.2 v1(81.51,20.21) ; C16.2 v1(12.31,41.98) 12.52,41.98 12.9,42.37 v1(13.13,42.6) v1(13.93,42.6) ; D38.1 v1(127.85,6.91) ; v1(117.86,70.79) U15.3 U15.8 v1(117.86,73.23) ; v1(107.06,46.99) 107.06,47.55 107.39,47.88 ; J20.40 133.22,17.32 v1(133.6,16.94) ; C110.2 v1(96.14,44.12) ; v1(78.87,60.93) 78.69,61.12 J3.250 ; R133.2 v1(96.14,43.1) ; v1(87.22,33.99) 87.22,33.22 C57.2 ; v1(87.22,33.99) v1(88.22,33.99) v1(89.22,33.99) v1(90.22,33.99) v1(91.22,33.99) v1(91.22,32.99) ; v1(87.22,33.99) R62.2 ; v1(95.77,66.43) 94.19,64.85 J3.312 ; J15.21 v1(5.54,41.55) ; v1(42.78,80.95) C70.2 R86.2 ; v1(10.92,13.96) C152.2 v1(11.68,13.3) ; D37.1 132.76,6.91 v1(132.72,6.86) ; J20.35 v1(131.22,9.14) ; U35.2 v1(25.02,21.54) ; C37.2 v1(67.32,20.19) ; v1(134.99,70.85) U18.3 U18.8 v1(134.99,73.16) ; v1(144.48,23.01) 144.44,23.05 J13.22 142.58,23.05 v1(142.49,22.96) ; 26.39,79.85 D20.1 27.16,80.62 v1(27.16,80.8) ; J3.92 v1(37.19,65.15) ; C123.2 v1(103.25,50.6) ; 68.69,58.32 J3.210 68.69,64.86 68.28,65.28 v1(67.92,65.28) ; 26.82,72.75 28.98,72.75 ; v1(124.71,20.5) 124.42,20.21 J20.18 ; v1(77.44,20.21) R66.2 ; v2(10.56,56.66) 12.03,56.66 14.35,54.34 14.35,52.31 14.69,51.97 17.31,51.97 v1(17.44,52.1) ; J3.22 19.69,60.25 19.44,60 J3.21 ; Q18.2 v1(107.01,59.03) ; v1(98.2,50.6) 98.2,49.67 Y4.2 ; v1(98.2,50.6) v1(99.2,50.6) v1(100.2,50.6) C131.2 ; U19.39 v1(103.58,38.4) ; v1(31.39,78.71) 31.37,78.74 U16.3 U16.8 v1(31.37,81.31) 31.37,81.84 30.55,82.65 J10.A1 30.55,83.62 ; v1(84.07,15.01) D28.1 v1(84.07,13.5) ; v1(90.72,28) 90.71,28.01 R80.2 C147.2 ; J3.220 71.19,62.36 v1(71.3,62.26) ; J3.19 18.94,60.06 19.19,60.31 J3.20 ; J3.260 81.19,64.96 80.69,65.46 v1(80.69,66.06) ; v1(91.22,32.99) v1(91.22,31.99) v1(91.22,30.99) v1(91.22,29.99) 91.22,29.97 90.88,29.62 89.53,29.62 88.76,30.39 Y3.2 88.34,30.13 v1(88.34,29.54) 88.11,29.54 87.72,29.93 C58.2 ; v1(91.22,32.99) 90.4,32.99 Y3.4 ; C137.2 148.07,34.3 v1(148.22,34.15) ; J3.213 68.94,54.5 v1(69.01,54.43) 69.01,51.61 69.65,50.98 ; Q19.2 v1(103.42,59.75) ; C42.2 v1(71.49,29.93) 71.91,29.93 Y2.2 72.53,30.39 73.3,29.62 74.64,29.62 74.99,29.97 v1(74.99,29.99) v1(74.99,30.99) v1(74.99,31.99) v1(74.99,32.99) ; J3.191 63.44,54.03 63.45,54.03 ; 79.88,37.67 84.81,37.67 ; v1(137.07,20.29) 137.22,20.14 J20.50 v1(137.22,17.24) ; J13.16 144.5,20.05 ; U34.2 v1(31.24,21.54) ; v1(64.95,54.03) 64.94,54.03 J3.197 ; v1(82.3,13.5) D27.1 v1(82.3,15.01) ; 25.05,83.71 J10.A12 v1(25.05,82.19) ; D34.1 v1(2.67,75.29) ; C186.2 v1(66.67,11.16) ; v1(74.43,28.02) 74.43,28.01 R56.2 C150.2 ; D40.1 v1(118.21,6.91) ; v1(87.63,13.5) D58.1 87.63,15.01 87.16,15.48 C134.2 C133.2 v1(87.16,17.78) ; v1(57.69,62.44) 57.69,62.44 J3.166 57.69,65.11 v1(58.2,65.61) ; R194.2 v1(68.45,14.97) ; 74.9,62.13 75.19,62.41 J3.236 ; J20.29 v1(128.82,9.14) ; 92,62.1 91.69,62.41 v1(91.69,62.41) 91.69,62.41 J3.302 91.69,64.94 ; C176.2 v1(5.08,77.7) ; C23.2 v1(138.18,8.78) ; v1(18.06,69.57) 18.06,70.09 C87.1 ; v1(84.55,22.53) C51.2 C50.2 ; J3.203 66.44,50.46 v1(66.32,50.34) ; C120.2 v1(102.36,33.63) ; v1(123.24,60.5) v1(123.24,59.19) v1(123.24,53.26) ; J3.299 90.44,54.53 v1(90.57,54.41) v1(90.57,53.48) ; v1(51.69,62.44) J3.150 ; J3.255 v1(79.44,54.43) ; C77.2 v1(44.45,82.61) ; v1(127.78,23.36) 127.38,23.36 C173.2 ; v1(68.22,22.53) 68.32,22.62 C34.2 C35.2 ; R214.2 v1(35.06,14.84) ; C142.2 C141.2 123.44,40.54 123.65,40.74 v1(123.75,40.74) ; v1(133.2,70.84) 133.38,70.66 133.38,68.64 131.79,67.06 v1(131.47,67.06) ; 103.26,52.25 96.82,52.25 ; 103.26,52.25 R165.2 v1(101.91,52.84) ; 103.26,52.25 v1(107.14,52.25) ; J3.27 20.94,57.42 v1(21.29,57.76) 21.26,57.79 v1(21.26,59.44) v1(21.26,60.44) v1(21.26,61.44) v1(21.26,62.44) 21.19,62.5 J3.28 ; R218.2 43.08,15.1 v1(43.08,14.85) ; J3.108 v1(41.19,65.15) ; D14.1 v1(43.45,87.96) ; v1(76.96,50.6) 76.94,50.62 v1(76.94,53.43) v1(76.94,54.43) J3.245 ; v1(8.2,22.3) 8.2,22.76 ; J3.182 61.69,62.44 v1(60.73,61.48) ; C49.2 84.82,21.59 v1(85.2,21.59) ; v1(25.3,85.45) J10.B1 ; D46.1 90.06,69.3 v1(89.86,69.1) 89.79,69.03 D48.2 ; v1(24.25,82.19) 24.51,81.94 U14.8 U14.3 ; Q20.2 v1(109.97,58.94) ; C175.2 135.64,23.76 ; R14.2 v1(105.77,15.76) ; J3.265 v1(81.94,54.43) ; v1(78.46,20.21) R65.2 ; C151.2 v1(9.91,13.96) ; J13.7 v1(144.5,15.55) ; DN1.3 v1(37.97,12.53) ; C226.2 88.27,68.7 v1(87.86,69.1) ; J14.18 v1(5.46,20.85) ; D45.1 88.51,69.46 v1(88.86,69.1) ; J3.231 v1(73.44,54.43) 73.44,53.23 v1(73.76,52.91) v1(73.76,52.11) ; J13.6 v1(142.49,15.05) ; C88.2 R100.2 20.2,71.66 v1(20.7,72.16) ; v1(130.96,24.77) 130.51,24.32 D33.2 ; D32.2 v1(133.55,24.87) ; J15.23 5.79,42.55 v1(5.54,42.8) 5.79,43.05 J15.24 ; C136.2 148.07,32.31 v1(148.21,32.44) ; C52.2 83.52,20.82 v1(83.52,20.19) ; C114.2 114.24,44.12 ; D57.2 v1(33.27,12.47) ; v1(53.19,58.25) 53.93,58.25 54.44,57.74 J3.161 ; v1(57.2,57.25) 57.44,57.01 J3.167 ; J3.196 65.19,65.2 v1(65.19,65.2) ; v1(103.56,52.84) R151.2 v1(105.07,52.84) ; Q2.2 v1(106.39,21.07) ; v1(29.29,79.27) 29.29,79.71 D19.1 ; Q8.2 v1(111.94,55.31) ; Q17.2 v1(69.89,16.12) ; C61.2 v1(76.78,33.4) ; C38.2 61.22,26.81 v1(61.16,26.86) ; v1(87.44,53.48) 86.94,53.98 v1(86.94,54.41) J3.285 ; v1(80.52,13.5) D26.1 v1(80.52,15.01) ; v1(74.99,32.99) 74.16,32.99 Y2.4 ; U36.5 v1(39.18,17.01) ; J13.25 144.49,24.55 ; R45.2 v1(65.28,20.21) ; v1(85.85,15.01) D29.1 v1(85.85,13.5) ; R104.1 v1(77.89,49.01) ; v1(146.84,25.63) 147.12,25.91 ; v1(71.09,57.89) 70.43,57.89 ; J20.15 v1(120.02,9.14) ; Q21.2 102.11,54.81 v1(101.7,54.81) ; J20.27 v1(128.02,9.14) ; v1(114.24,41.07) C112.2 C113.2 ; v1(43.69,61.44) 43.19,61.94 J3.116 ; J20.9 v1(117.62,9.14) ; C90.2 v1(32.11,70.49) ; v1(47.16,72.65) R94.2 46.35,71.51 C84.2 ; J10.B12 30.81,83.75 ; v1(100.97,50.6) 101.23,50.34 C127.2 ; v1(68.97,21.59) 68.59,21.59 C33.2 ; J20.4 v1(115.62,20.06) ; v1(72.96,47.65) v1(72.16,47.65) ; v1(83.69,62.44) 83.69,62.44 J3.270 ; 144.73,25.7 144.39,26.05 J13.28 v1(142.44,26.05) ; R85.1 v1(42.78,78.91) ; C122.2 v1(104.39,33.63) ; J3.70 v1(31.69,65.15) ; C126.2 v1(113.53,38.38) ; J3.314 v1(94.44,54.54) ; J3.60 29.19,64.98 29.02,65.15 v1(28.69,65.15) ; C113.2 v1(114.24,42.09) ; C113.2 C115.2 114.24,43.1 ; C185.2 v1(61.84,11.16) ; J20.37 v1(132.02,9.14) ; J3.9 v1(16.44,54.1) ; LED1.1 v1(137.88,2.24) ; U19.24 v1(102.58,44.83) ; R90.2 v1(47.01,70.22) ; v1(10.97,33.2) 10.92,33.15 C153.2 ; C177.2 v1(3.94,77.7) ; v1(142.47,21.55) J13.19 144.49,21.55 ; D39.1 v1(125.01,6.91) ; C116.2 v1(104.27,50.6) ; J3.44 v1(25.19,65.15) ; J3.13 v1(17.44,54.1) ; D25.2 v1(21.73,12.47) ; J20.26 127.62,19.73 v1(128.3,20.4) ; U37.5 v1(46.84,17.01) ; v1(85.44,46.69) v1(85.44,54.43) J3.279 ; D47.2 v1(28.2,12.47) ; 111.66,43.92 111.07,43.33 U19.10 108.47,43.33 v1(108.46,43.33) ; J3.305 v1(91.94,54.54) ; 73.36,51.41 71.55,51.41 ; J3.115 v1(42.94,54.54) ; v1(69.94,52.83) v1(69.94,54.43) J3.217 ; v1(125.62,9.14) J20.21 ; J15.4 v1(5.55,33.05) ; C56.2 77.45,26.81 v1(77.39,26.86) ; v1(25.65,69.6) 26.2,70.14 26.84,70.14 26.94,70.23 U38.7 ; v1(5.21,51.77) 5.31,51.87 J18.4 v1(11.2,51.87) ; R137.1 v1(78.96,49.01) ; J13.8 142.49,16.05 ; R43.2 v1(62.23,20.21) ; U34.8 v1(32.51,14.02) ; U4.4 v1(140.75,4.25) ; J3.177 v1(59.94,52.3) ; C65.2 v1(42.79,79.93) ; C124.2 v1(96.14,42.09) ; DN2.3 v1(45.59,12.76) ; C183.2 v1(58.81,11.16) ; C187.2 v1(63.64,11.16) ; U35.8 v1(26.29,14.02) ; C117.2 v1(107.44,33.63) ; v1(49.94,54.54) 49.94,54.54 J3.143 49.94,56.94 50.25,57.25 v1(50.94,57.25) ; R44.2 v1(66.29,20.21) ; J14.24 v1(5.55,23.85) ; J20.43 v1(134.42,9.14) ; J3.284 v1(87.19,62.44) ; J14.21 v1(5.46,22.35)
  TOP w0.305: U22.5 v1(128.41,30.26)
  TOP w0.381: 143.47,73 SW2.1 ; SW2.1 145.43,73 ; SW2.1 144.45,73.98 ; SW2.1 144.45,72.02 ; 111.3,62.65 SS7.1 ; SS7.1 114.12,59.82 ; SS7.1 114.12,65.48 ; J15.26 5.03,29.85 ; J15.26 3.86,28.87 ; J15.26 3.86,30.83 ; J20.54 112.83,11.1 ; J20.54 111.57,12.58 ; J20.54 110.32,11.1 ; J20.54 111.57,9.62 ; SW3.3 147.38,80.03 ; SW3.3 145.42,80.03 ; SW3.3 146.4,79.05 ; SW3.3 146.4,81.01 ; 2.55,69.82 J5.2 ; J5.2 1.92,70.45 ; J5.2 2.55,71.07 ; J33.2 98.85,80.9 ; J33.2 98.32,80.37 ; J33.2 97.79,80.9 ; J33.2 98.32,81.42 ; 140.87,9.62 J20.53 ; J20.53 140.87,12.58 ; J20.53 139.62,11.1 ; J20.53 142.13,11.1 ; 100.21,12.53 J2.2 ; J2.2 100.92,15.27 D1.2 ; J2.2 100.92,11.83 ; J30.6 83.72,4.44 ; J30.6 82.99,3.71 ; J30.6 84.45,3.71 ; J30.6 83.72,2.98 ; 144.73,53.18 J32.9 ; J32.9 144.73,55.13 ; J32.9 143.75,54.15 ; J32.9 145.71,54.15 ; 2.68,10.65 J14.26 ; J14.26 3.86,11.63 ; J14.26 3.86,9.67 ; J14.26 v1(5.23,10.65) ; 89.16,13.09 SS6.1 ; SS6.1 92.44,9.82 ; SS6.1 95.72,13.09 ; SS6.1 92.44,16.37 ; 114.69,78.15 J11.7 ; J11.7 115.42,78.88 ; J11.7 114.69,79.61 ; J11.7 113.96,78.88 ; J23.6 69.5,3.71 ; J23.6 68.77,4.44 ; J23.6 68.77,2.98 ; J23.6 68.04,3.71 ; 96.79,79.15 J33.5 ; J33.5 97.32,79.68 ; J33.5 97.85,79.15 ; J33.5 97.32,78.63 ; 146.29,49.07 J32.14 ; J32.14 147.27,50.05 ; J32.14 148.25,49.07 ; J32.14 147.27,48.1 ; J18.25 3.86,64.55 ; J18.25 5.03,63.57 ; J18.25 2.68,63.57 ; SS5.1 16.44,16.37 ; SS5.1 19.72,13.09 ; SS5.1 13.16,13.09 ; SS5.1 16.44,9.82 ; J25.4 109.62,4.44 ; J25.4 108.89,3.71 ; J25.4 109.62,2.98 ; J25.4 110.34,3.71 ; 145.42,69.06 SW1.3 ; SW1.3 146.4,70.04 ; SW1.3 147.38,69.06 ; SW1.3 146.4,68.09 ; 12.24,79.67 13.16,79.67 ; 13.16,79.67 13.16,81.2 ; 13.16,79.67 13.16,78.15 ; 13.16,79.67 14.09,79.67 ; 76.77,2.98 J23.2 ; J23.2 76.77,4.44 ; J23.2 76.04,3.71 ; J23.2 77.5,3.71 ; SW1.1 145.43,67.51 ; SW1.1 144.45,66.54 ; SW1.1 143.47,67.51 ; SW1.1 144.45,68.49 ; 97.79,77.43 J33.8 ; J33.8 98.85,77.43 ; J33.8 98.32,77.96 ; J33.8 98.32,76.9 ; J11.4 111.92,80.38 ; J11.4 111.19,81.11 ; J11.4 111.19,79.65 ; J11.4 110.46,80.38 ; J23.4 72.77,4.44 ; J23.4 72.77,2.98 ; J23.4 73.5,3.71 ; J23.4 72.04,3.71 ; 58.51,6.05 J24.2 ; J24.2 60.66,6.05 ; J24.2 59.59,4.97 ; J24.2 59.59,7.13 ; J11.13 111.92,77.18 ; J11.13 111.19,77.91 ; J11.13 111.19,76.45 ; J11.13 110.46,77.18 ; J18.26 3.86,49.65 ; J18.26 2.68,48.67 ; J18.26 5.03,48.67 ; J18.26 3.86,47.69 ; J26.4 98.67,4.44 ; J26.4 97.94,3.71 ; J26.4 98.67,2.98 ; J26.4 99.4,3.71 ; C204.2 29.58,70.23 U38.7 ; 145.42,74.55 SW2.3 ; SW2.3 146.4,73.57 ; SW2.3 146.4,75.53 ; SW2.3 147.38,74.55 ; 96.79,72.22 J33.17 97.85,72.22 ; 96.79,75.69 J33.11 ; J33.11 97.85,75.69 ; J33.11 97.32,75.16 ; J33.11 97.32,76.22 ; SW3.1 145.43,78.48 ; SW3.1 144.45,79.46 ; SW3.1 143.47,78.48 ; SW3.1 144.45,77.5 ; 145.01,10.4 J13.32 ; J13.32 146.19,11.37 ; J13.32 146.19,9.42 ; J13.32 147.37,10.4 ; 114.69,74.95 J11.16 113.96,75.68 ; 146.29,43.99 J32.18 ; J32.18 147.27,44.97 ; J32.18 147.27,43.02 ; J32.18 148.25,43.99 ; J15.25 3.86,45.73 ; J15.25 3.86,43.77 ; J15.25 2.68,44.75 ; J15.25 5.03,44.75 ; 48.16,4.97 J24.5 ; J24.5 47.08,6.05 ; J24.5 48.16,7.13 ; J24.5 49.23,6.05 ; 130.36,74.52 J12.4 ; J12.4 130.36,76.48 ; J12.4 131.33,75.5 ; J12.4 129.38,75.5 ; 147.27,58.26 J32.6 ; J32.6 146.29,59.23 ; J32.6 148.25,59.23 ; J32.6 147.27,60.21 ; v1(0.71,73.04) 0.86,72.89 U29.3 ; J3.316 12.72,60.85 ; J3.316 11.04,58.09 ; J3.316 9.36,60.85 ; J3.316 11.04,63.6 ; 3.86,24.57 J14.25 ; J14.25 5.03,25.55 ; J14.25 3.86,26.53 ; 18.46,79.67 18.46,81.2 ; 18.46,79.67 17.54,79.67 ; 18.46,79.67 19.39,79.67 ; 18.46,79.67 18.46,78.15 ; 129.38,78.5 J12.10 ; J12.10 130.36,79.48 ; J12.10 130.36,77.52 ; J12.10 131.33,78.5 ; 147.37,29.2 J13.31 145.01,29.2 ; 135.5,62.65 SS8.1 ; SS8.1 141.15,62.65 ; SS8.1 138.32,59.82 ; SS8.1 138.32,65.48 ; U29.1 0.86,74.19 v1(0.71,74.04) ; J21.3 1.78,80.58 ; J21.3 0.8,79.6 ; J21.3 1.78,78.62 ; J21.3 2.76,79.6 ; J3.315 99.52,60.85
  TOP w0.508: C17.2 8.32,40.91 ; J3.315 97.84,57.73
  GND02 w0.381: SS5.1 19.22,13.09 ; SS5.1 16.44,10.32 ; SS5.1 13.66,13.09 ; SS5.1 16.44,15.87 ; J2.2 101.62,12.53 ; J2.2 100.21,12.53 ; J2.2 100.92,11.83 ; J2.2 100.92,13.24 ; 111.19,76.45 J11.13 ; J11.13 111.19,77.91 ; J11.13 110.46,77.18 ; J11.13 111.92,77.18 ; J32.9 144.73,55.13 ; J32.9 145.71,54.15 ; J32.9 144.73,53.18 ; J32.9 143.75,54.15 ; 113.96,78.88 J11.7 ; J11.7 114.69,78.15 ; J11.7 114.69,79.61 ; J11.7 115.42,78.88 ; 97.74,77.43 J33.8 98.9,77.43 ; 59.59,4.97 J24.2 ; J24.2 58.51,6.05 ; J24.2 60.66,6.05 ; J24.2 59.59,7.13 ; 114.12,60.47 SS7.1 ; SS7.1 114.12,64.83 ; SS7.1 116.3,62.65 ; SS7.1 111.95,62.65 ; SW1.3 146.4,70.04 ; SW1.3 146.4,68.09 ; SW1.3 145.42,69.06 ; SW1.3 147.38,69.06 ; 146.29,43.99 J32.18 ; J32.18 147.27,43.02 ; J32.18 148.25,43.99 ; J32.18 147.27,44.97 ; 72.77,2.98 J23.4 ; J23.4 72.04,3.71 ; J23.4 73.5,3.71 ; J23.4 72.77,4.44 ; SW3.1 145.43,78.48 ; SW3.1 144.45,77.5 ; SW3.1 144.45,79.46 ; SW3.1 143.47,78.48 ; 76.77,2.98 J23.2 ; J23.2 76.04,3.71 ; J23.2 77.5,3.71 ; J23.2 76.77,4.44 ; 1.92,70.45 J5.2 ; J5.2 2.55,71.07 ; J5.2 2.55,69.82 ; 130.36,74.52 J12.4 ; J12.4 131.33,75.5 ; J12.4 130.36,76.48 ; J12.4 129.38,75.5 ; 146.4,79.05 SW3.3 ; SW3.3 145.42,80.03 ; SW3.3 147.38,80.03 ; SW3.3 146.4,81.01 ; 147.27,48.1 J32.14 ; J32.14 147.27,50.05 ; J32.14 148.25,49.07 ; J32.14 146.29,49.07 ; 146.29,59.23 J32.6 ; J32.6 147.27,60.21 ; J32.6 147.27,58.26 ; J32.6 148.25,59.23 ; SS8.1 138.32,64.83 ; SS8.1 136.15,62.65 ; SS8.1 138.32,60.47 ; SS8.1 140.5,62.65 ; J33.2 98.9,80.9 ; J33.2 97.74,80.9 ; J33.2 98.32,81.47 ; 68.77,2.98 J23.6 ; J23.6 69.5,3.71 ; J23.6 68.77,4.44 ; J23.6 68.04,3.71 ; J24.5 49.23,6.05 ; J24.5 47.08,6.05 ; J24.5 48.16,4.97 ; J24.5 48.16,7.13 ; 144.45,72.02 SW2.1 ; SW2.1 145.43,73 ; SW2.1 143.47,73 ; SW2.1 144.45,73.98 ; 130.36,77.52 J12.10 ; J12.10 129.38,78.5 ; J12.10 131.33,78.5 ; J12.10 130.36,79.48 ; J21.3 1.78,80.58 ; J21.3 2.76,79.6 ; J21.3 1.78,78.62 ; J21.3 0.8,79.6 ; SW1.1 144.45,68.49 ; SW1.1 144.45,66.54 ; SW1.1 143.47,67.51 ; SW1.1 145.43,67.51 ; 82.99,3.71 J30.6 ; J30.6 83.72,2.98 ; J30.6 84.45,3.71 ; J30.6 83.72,4.44 ; J11.16 114.69,76.41 ; J11.16 115.42,75.68 ; J11.16 113.96,75.68 ; J11.16 114.69,74.95 ; 110.46,80.38 J11.4 ; J11.4 111.19,81.11 ; J11.4 111.19,79.65 ; J11.4 111.92,80.38 ; 96.74,75.69 J33.11 97.9,75.69 ; 13.16,79.67 14.09,79.67 ; 13.16,79.67 13.16,81.2 ; 13.16,79.67 12.24,79.67 ; 13.16,79.67 13.16,78.15 ; J26.4 99.4,3.71 ; J26.4 98.67,2.98 ; J26.4 97.94,3.71 ; J26.4 98.67,4.44 ; 145.42,74.55 SW2.3 ; SW2.3 147.38,74.55 ; SW2.3 146.4,75.53 ; SW2.3 146.4,73.57 ; 96.74,72.22 J33.17 97.9,72.22 ; SS6.1 95.22,13.09 ; SS6.1 92.44,15.87 ; SS6.1 89.66,13.09 ; SS6.1 92.44,10.32 ; 18.46,78.15 18.46,79.67 ; 18.46,79.67 18.46,81.2 ; 18.46,79.67 19.39,79.67 ; 18.46,79.67 17.54,79.67 ; 96.74,79.15 J33.5 97.9,79.15 ; 109.62,2.98 J25.4 ; J25.4 110.34,3.71 ; J25.4 109.62,4.44 ; J25.4 108.89,3.71
  ART03 w0.203: 4.93,39.01 4.45,38.53 4.17,38.53
  ART03 w0.254: v1(41.19,65.15) v1(39.69,65.15) v1(37.19,65.15) ; 12.67,11.68 15,11.68 16.23,12.9 16.44,13.09 SS5.1 ; v1(13.41,48.29) 13.36,48.23 13.36,44.43 14.31,43.48 ; v1(45.63,67.26) 45.15,66.78 v1(40.19,66.78) v1(39.19,66.78) v1(38.19,66.78) v1(37.19,66.78)
  ART03 w0.381: 130.36,74.52 J12.4 ; J12.4 130.36,76.48 ; J12.4 131.33,75.5 ; J12.4 129.38,75.5 ; 18.46,79.67 18.46,81.2 ; 18.46,79.67 19.39,79.67 ; 18.46,79.67 17.54,79.67 ; 113.96,75.68 J11.16 ; J11.16 114.69,74.95 ; J11.16 115.42,75.68 ; J11.16 114.69,76.41 ; J11.4 111.92,80.38 ; J11.4 111.19,79.65 ; J11.4 110.46,80.38 ; J11.4 111.19,81.11 ; J32.14 147.27,50.05 ; J32.14 147.27,48.1 ; J32.14 148.25,49.07 ; J32.14 146.29,49.07 ; 110.46,77.18 J11.13 ; J11.13 111.19,76.45 ; J11.13 111.92,77.18 ; J11.13 111.19,77.91 ; SS5.1 19.22,13.09 ; SS5.1 13.66,13.09 ; SS5.1 16.44,10.32 ; SS5.1 16.44,15.87 ; SS8.1 140.5,62.65 ; SS8.1 136.15,62.65 ; SS8.1 138.32,64.83 ; SS8.1 138.32,60.47 ; 96.74,72.22 J33.17 97.9,72.22 ; J11.7 114.69,79.61 ; J11.7 113.96,78.88 ; J11.7 115.42,78.88 ; J11.7 114.69,78.15 ; 97.74,77.43 J33.8 98.9,77.43 ; J24.5 48.16,7.13 ; J24.5 47.08,6.05 ; J24.5 49.23,6.05 ; J24.5 48.16,4.97 ; 144.45,77.5 SW3.1 ; SW3.1 145.43,78.48 ; SW3.1 144.45,79.46 ; SW3.1 143.47,78.48 ; 92.44,10.32 SS6.1 ; SS6.1 89.66,13.09 ; SS6.1 95.22,13.09 ; 146.4,79.05 SW3.3 ; SW3.3 145.42,80.03 ; SW3.3 147.38,80.03 ; SW3.3 146.4,81.01 ; SW1.3 146.4,70.04 ; SW1.3 146.4,68.09 ; SW1.3 145.42,69.06 ; SW1.3 147.38,69.06 ; J32.6 148.25,59.23 ; J32.6 147.27,60.21 ; J32.6 146.29,59.23 ; J32.6 147.27,58.26 ; 13.16,79.67 14.09,79.67 ; 13.16,79.67 12.24,79.67 ; 13.16,79.67 13.16,81.2 ; 13.16,79.67 13.16,78.15 ; 144.45,66.54 SW1.1 ; SW1.1 144.45,68.49 ; SW1.1 145.43,67.51 ; SW1.1 143.47,67.51 ; 145.42,74.55 SW2.3 ; SW2.3 147.38,74.55 ; SW2.3 146.4,75.53 ; SW2.3 146.4,73.57 ; J2.2 101.62,12.53 ; J2.2 100.92,13.24 ; J2.2 100.92,11.83 ; J2.2 100.21,12.53 ; 114.12,60.47 SS7.1 ; SS7.1 114.12,64.83 ; SS7.1 111.95,62.65 ; SS7.1 116.3,62.65 ; SW2.1 145.43,73 ; SW2.1 144.45,73.98 ; SW2.1 144.45,72.02 ; SW2.1 143.47,73 ; 1.92,70.45 J5.2 ; J5.2 2.55,71.07 ; J5.2 2.55,69.82 ; 144.73,53.18 J32.9 ; J32.9 144.73,55.13 ; J32.9 143.75,54.15 ; J32.9 145.71,54.15 ; J32.18 147.27,44.97 ; J32.18 147.27,43.02 ; J32.18 148.25,43.99 ; J32.18 146.29,43.99 ; J21.3 2.76,79.6 ; J21.3 0.8,79.6 ; J21.3 1.78,78.62 ; J21.3 1.78,80.58 ; J33.2 98.32,81.47 ; J33.2 97.74,80.9 ; J33.2 98.9,80.9 ; 130.36,77.52 J12.10 ; J12.10 130.36,79.48 ; J12.10 131.33,78.5 ; J12.10 129.38,78.5 ; 96.74,75.69 J33.11 97.9,75.69 ; 96.74,79.15 J33.5 97.9,79.15
  PWR04 w0.381: 144.45,72.02 SW2.1 ; SW2.1 143.47,73 ; SW2.1 144.45,73.98 ; SW2.1 145.43,73 ; J32.14 147.27,50.05 ; J32.14 146.29,49.07 ; J32.14 148.25,49.07 ; J32.14 147.27,48.1 ; SW1.3 146.4,70.04 ; SW1.3 145.42,69.06 ; SW1.3 147.38,69.06 ; 114.69,74.95 J11.16 ; J11.16 115.42,75.68 ; J11.16 113.96,75.68 ; J11.16 114.69,76.41 ; 143.47,78.48 SW3.1 ; SW3.1 144.45,77.5 ; SW3.1 144.45,79.46 ; SW3.1 145.43,78.48 ; 1.78,78.62 J21.3 ; J21.3 0.8,79.6 ; J21.3 2.76,79.6 ; J21.3 1.78,80.58 ; 146.29,43.99 J32.18 ; J32.18 147.27,44.97 ; J32.18 148.25,43.99 ; J32.18 147.27,43.02 ; 12.24,79.67 13.16,79.67 ; 13.16,79.67 13.16,81.2 ; 13.16,79.67 13.16,78.15 ; 13.16,79.67 14.09,79.67 ; 17.54,79.67 18.46,79.67 ; 18.46,79.67 19.39,79.67 ; 18.46,79.67 18.46,78.15 ; 18.46,79.67 18.46,81.2 ; J32.9 145.71,54.15 ; J32.9 144.73,53.18 ; J32.9 144.73,55.13 ; J32.9 143.75,54.15 ; 111.19,76.45 J11.13 ; SW2.3 147.38,74.55 ; SW2.3 145.42,74.55 ; SW2.3 146.4,75.53 ; SW2.3 146.4,73.57 ; 146.4,79.05 SW3.3 ; SW3.3 145.42,80.03 ; SW3.3 147.38,80.03 ; SW3.3 146.4,81.01 ; J12.4 130.36,76.48 ; J12.4 131.33,75.5 ; J12.4 129.38,75.5 ; J12.4 130.36,74.52
  GND05 w0.381: J23.4 73.5,3.71 ; J23.4 72.77,2.98 ; J23.4 72.04,3.71 ; J23.4 72.77,4.44 ; 143.47,67.51 SW1.1 ; SW1.1 144.45,66.54 ; SW1.1 144.45,68.49 ; SW1.1 145.43,67.51 ; SW3.1 144.45,79.46 ; SW3.1 145.43,78.48 ; SW3.1 144.45,77.5 ; SW3.1 143.47,78.48 ; 1.92,70.45 J5.2 ; J5.2 2.55,69.82 ; J5.2 2.55,71.07 ; 17.54,79.67 18.46,79.67 ; 18.46,79.67 18.46,81.2 ; 18.46,79.67 19.39,79.67 ; 18.46,79.67 18.46,78.15 ; J23.2 76.77,4.44 ; J23.2 76.77,2.98 ; J23.2 77.5,3.71 ; J23.2 76.04,3.71 ; SW2.1 145.43,73 ; SW2.1 143.47,73 ; SW2.1 144.45,73.98 ; SW2.1 144.45,72.02 ; J33.2 98.32,81.47 ; J33.2 97.74,80.9 ; J33.2 98.9,80.9 ; J25.4 110.34,3.71 ; J25.4 108.89,3.71 ; J25.4 109.62,4.44 ; J25.4 109.62,2.98 ; 143.75,54.15 J32.9 ; J32.9 144.73,53.18 ; J32.9 144.73,55.13 ; J32.9 145.71,54.15 ; J11.13 111.92,77.18 ; J11.13 111.19,77.91 ; J11.13 111.19,76.45 ; J11.13 110.46,77.18 ; SS6.1 92.44,15.87 ; SS6.1 92.44,10.32 ; SS6.1 89.66,13.09 ; SS6.1 95.22,13.09 ; J32.6 148.25,59.23 ; J32.6 146.29,59.23 ; J32.6 147.27,58.26 ; J32.6 147.27,60.21 ; 129.38,75.5 J12.4 ; J12.4 130.36,74.52 ; J12.4 130.36,76.48 ; J12.4 131.33,75.5 ; SS8.1 138.32,64.83 ; SS8.1 138.32,60.47 ; SS8.1 136.15,62.65 ; SS8.1 140.5,62.65 ; 16.44,10.32 SS5.1 ; SS5.1 16.44,15.87 ; SS5.1 19.22,13.09 ; SS5.1 13.66,13.09 ; 114.69,78.15 J11.7 ; J11.7 115.42,78.88 ; J11.7 113.96,78.88 ; J11.7 114.69,79.61 ; J32.18 147.27,44.97 ; J32.18 148.25,43.99 ; J32.18 146.29,43.99 ; J32.18 147.27,43.02 ; 0.8,79.6 J21.3 ; J21.3 1.78,80.58 ; J21.3 2.76,79.6 ; J21.3 1.78,78.62 ; J26.4 98.67,4.44 ; J26.4 97.94,3.71 ; J26.4 99.4,3.71 ; J26.4 98.67,2.98 ; 146.4,73.57 SW2.3 ; SW2.3 145.42,74.55 ; SW2.3 146.4,75.53 ; SW2.3 147.38,74.55 ; J11.4 111.92,80.38 ; J11.4 111.19,81.11 ; J11.4 110.46,80.38 ; J11.4 111.19,79.65 ; J2.2 100.92,13.24 ; J2.2 100.21,12.53 ; J2.2 100.92,11.83 ; J2.2 101.62,12.53 ; 146.4,79.05 SW3.3 ; SW3.3 147.38,80.03 ; SW3.3 145.42,80.03 ; SW3.3 146.4,81.01 ; 114.12,60.47 SS7.1 ; SS7.1 111.95,62.65 ; SS7.1 116.3,62.65 ; SS7.1 114.12,64.83 ; J24.5 48.16,7.13 ; J24.5 49.23,6.05 ; J24.5 48.16,4.97 ; J24.5 47.08,6.05 ; 145.42,69.06 SW1.3 ; SW1.3 146.4,70.04 ; SW1.3 146.4,68.09 ; SW1.3 147.38,69.06 ; 130.36,77.52 J12.10 ; J12.10 129.38,78.5 ; J12.10 130.36,79.48 ; J12.10 131.33,78.5 ; J24.2 59.59,7.13 ; J24.2 60.66,6.05 ; J24.2 58.51,6.05 ; J24.2 59.59,4.97 ; 13.16,79.67 14.09,79.67 ; 13.16,79.67 13.16,78.15 ; 13.16,79.67 13.16,81.2 ; 13.16,79.67 12.24,79.67 ; J32.14 147.27,50.05 ; J32.14 146.29,49.07 ; J32.14 147.27,48.1 ; J32.14 148.25,49.07 ; J30.6 83.72,4.44 ; J30.6 84.45,3.71 ; J30.6 83.72,2.98 ; J30.6 82.99,3.71 ; 97.9,79.15 J33.5 96.74,79.15 ; 113.96,75.68 J11.16 ; J11.16 115.42,75.68 ; J11.16 114.69,74.95 ; J11.16 114.69,76.41 ; 97.9,72.22 J33.17 96.74,72.22 ; J23.6 68.77,4.44 ; J23.6 68.04,3.71 ; J23.6 69.5,3.71 ; J23.6 68.77,2.98 ; 96.74,75.69 J33.11 97.9,75.69 ; 98.9,77.43 J33.8 97.74,77.43
  BOTTOM w0.152: U9.13 25.63,61.75 25.63,62.97 C80.2 ; v1(10.06,22.35) 9.94,22.47 8.39,22.47 8.23,22.3 v1(8.2,22.3) ; 73.94,41.5 72.26,41.5 71.58,42.19
  BOTTOM w0.2: v1(28.67,61.43) U9.18
  BOTTOM w0.203: v1(24.44,57.25) 24.49,57.25 U9.4 v1(26.67,59.43) U9.18 ; v1(33.43,57.33) 33.43,58.7 34.87,60.15 34.87,62.28 36.44,63.86 42.06,63.86 45.11,66.91 45.11,72.95 ; U9.13 26.67,60.71 v1(26.67,60.43) ; R242.2 48.31,74.73 48.31,73.99 47.16,72.84 v1(47.16,72.65)
  BOTTOM w0.254: C191.2 52.84,19.68 C195.2 v1(53.49,19.69) ; C139.2 119.18,14.11 v1(119.3,14.24) ; D22.1 25.81,84.71 25.3,85.22 v1(25.3,85.45) ; C25.2 133.33,64 v1(132.97,64) ; C128.2 C111.2 v1(136.02,83.06) ; 27.05,72.75 28.96,72.75 ; R2.2 10.91,66.6 v2(10.3,67.22) ; J14.4 7.55,13.85 v1(7.65,13.94) ; v1(41.79,86.88) 41.8,86.87 C85.2 ; R51.2 v1(62.1,87.76) ; R161.2 122.8,18.42 v1(122.96,18.26) ; J17.18 5.35,34.55 v1(5.05,34.25) ; D3.1 v1(130.81,22.86) ; C90.2 v1(32.11,70.49) ; C95.2 v1(51.38,77.09) ; v1(47.16,72.65) 47.16,70.37 v1(47.01,70.22) 47.01,68.64 v1(45.63,67.26) ; C14.2 11.81,56.89 v2(11.81,57.68) 11.56,57.94 11.56,63.63 v2(11.94,64.01) ; J4.6 135.86,20.71 v1(136.27,20.29) ; D2.1 131.47,24 130.96,24.51 v1(130.96,24.77) ; R75.2 v1(81.66,87.76) ; C83.2 42.83,86.84 v1(42.79,86.88) ; C169.2 v1(130.05,34.54) ; C78.2 v1(32.06,60.96) 32.54,61.43 32.54,63.3 36.02,66.78 v1(37.19,66.78) v1(38.19,66.78) v1(39.19,66.78) ; C69.2 C67.2 C66.2 31.69,64.79 v1(31.69,65.15) ; C69.2 C68.2 ; C69.2 28.87,64.97 v1(28.69,65.15) ; v1(135.6,66.62) 136.44,66.62 D11.1 ; v1(114.91,26.92) 114.92,26.93 114.92,27.81 ; v1(9.02,19.2) 9.02,18.85 ; v1(5.46,22.35) J14.21 ; C210.2 30.06,68.75 31.09,68.75 v1(31.12,68.79) ; C168.2 v1(132.48,39.11) ; D16.1 50.05,76.45 C96.2 v1(50.06,77.09) ; D16.1 v1(49.01,77.18) ; D16.1 R242.2 ; v1(88.34,29.54) 88.86,29.02 C144.2 R79.2 89.99,29.11 90.87,29.99 v1(91.22,29.99) ; D7.1 v1(130.81,16.26) ; v1(18.06,69.57) 17.92,69.71 C87.1 ; D56.1 D51.1 v1(106.32,67.08) ; v1(32.06,58.42) 32.06,59.04 33.71,60.68 33.71,62.79 36.07,65.15 v1(37.19,65.15) v1(39.69,65.15) v1(41.19,65.15) 41.58,65.15 43.76,67.34 43.76,75.36 42.21,76.91 42.21,77.65 42.55,77.98 ; D15.1 v1(45.51,85.23) ; C129.2 v1(131.67,83.06) ; C20.2 128.3,19.29 v1(128.3,20.4) ; v1(101.24,67.08) D50.1 D31.1 ; v1(95.77,66.43) 95.91,66.29 D53.1 ; v1(39.76,84.55) 41.15,84.55 41.66,84.04 41.66,81.99 42.01,81.64 42.01,78.51 42.55,77.98 ; 42.55,77.98 45.59,77.98 45.98,77.59 v1(45.98,77.18) D17.1 R243.2 45.98,73.82 45.11,72.95 ; D52.1 D44.1 v1(103.78,67.08) ; J17.23 5.8,32.05 v1(5.55,31.8) 5.8,31.55 J17.24 ; v1(130.82,17.32) 130.91,17.32 130.98,17.4 D6.1 ; C194.2 53.07,13.88 v1(53.18,13.98) ; v1(11.2,51.87) 11.34,51.73 Q3.2 ; R101.2 v1(36.76,84.55) ; v1(28.55,80.83) 27.19,80.83 v1(27.16,80.8) ; R7.2 v1(16.36,65.25) ; C167.2 v1(127.51,38.1) ; J15.4 v1(5.55,33.05) ; U5.4 2.81,52.79 3.83,51.77 v1(5.21,51.77) ; R135.2 v1(131.2,86.69) ; C91.2 53.3,70.27 v1(53.72,70.69) 53.3,71.11 C92.2 ; L27.1 v1(98.28,83.99) ; R78.2 v1(83.35,80.82) ; R154.2 115.62,19.89 v1(115.62,20.06) ; v1(51.69,62.44) 51.69,62.54 52.55,63.4 57.18,63.4 57.69,62.89 v1(57.69,62.44) ; R176.2 v1(111.97,27.16) ; v1(10.72,19.19) 10.72,18.75 ; D4.1 v1(130.81,21.72) ; C79.2 v1(32.06,61.97) ; v1(115.44,70.99) 115.44,70.99 U17.8 U17.3 v1(115.44,73.53) ; 9.4,40.74 9.22,40.74 8.97,41 ; R50.2 v1(63.12,87.76) ; C29.2 6.09,48.97 v1(6.78,48.28) v1(6.78,47.28) v1(6.78,46.35) v1(5.16,46.35) v1(4.16,46.35) v1(2.39,46.35) v1(2.39,47.28) v1(2.39,48.28) v1(2.39,49.28) C28.2 ; L2.2 v1(15.49,85.27) ; v1(32.12,68.79) 32.16,68.75 32.72,68.75 C205.2 ; R92.2 44.86,83.01 v1(44.45,82.61) ; v1(9.98,19.19) 9.98,18.75 ; L12.2 v1(127.96,87.75) ; C21.2 D5.1 131.21,20.06 v1(130.82,20.06) ; J16.23 v1(5.55,12.85) ; C145.2 120.21,14.11 v1(120.08,14.24) ; R9.2 16.18,67.64 v2(16.18,68.22) ; C30.2 v1(129.29,64) ; C93.2 v1(34.92,81.41) ; v2(4.57,61.44) 4.57,57.45 5.08,56.95 C8.2 ; D8.1 v1(130.81,15.11) ; v1(71.49,29.93) 72.4,29.02 C149.2 R54.2 73.97,29.02 74.43,28.56 v1(74.43,28.02) ; 42.27,74.8 42.27,67.6 41.44,66.78 v1(40.19,66.78) ; Q12.2 17.33,50.99 v1(17.44,51.1) ; 61.04,57.58 v1(61.34,57.89) 61.34,58.85 61.65,59.16 ; D55.1 v1(108.86,68) ; C132.2 v1(138.81,87.69) ; J16.18 7.43,15.36 7.69,15.1 ; U1.1 v2(5.66,63.5) ; U13.2 v1(112.38,86.74) ; C27.2 v1(131.7,64) ; v1(80.69,66.06) 80.69,66.84 ; v1(98.7,67.08) D54.1 D49.1 ; C119.2 v1(131.67,84.07) ; v1(19.57,69.63) 20.2,69 C215.2 R226.2 ; U27.2 v1(129.92,36.32) ; R74.2 v1(82.68,87.76) ; J19.5 v1(134.92,33.43) ; C60.2 v1(81.07,80.77)
  BOTTOM w0.305: v1(48.16,72.65) 48.16,72.52 48.41,72.26 U11.9 ; U11.15 49.59,71.76 U11.8 ; J15.21 v1(5.54,41.55)
  BOTTOM w0.381: 18.46,78.15 18.46,79.67 ; 18.46,79.67 19.39,79.67 ; 18.46,79.67 18.46,81.2 ; 18.46,79.67 17.54,79.67 ; 143.47,67.51 SW1.1 ; SW1.1 145.43,67.51 ; SW1.1 144.45,66.54 ; SW1.1 144.45,68.49 ; C189.2 v1(28.02,15.78) ; 146.4,68.09 SW1.3 ; SW1.3 145.42,69.06 ; SW1.3 146.4,70.04 ; SW1.3 147.38,69.06 ; 110.46,77.18 J11.13 ; v1(46.84,19.82) 46.71,19.69 C199.2 ; 2.55,69.82 J5.2 ; J5.2 1.92,70.45 ; J5.2 2.55,71.07 ; J23.2 76.77,4.44 ; J23.2 77.5,3.71 ; J23.2 76.04,3.71 ; J11.16 115.42,75.68 ; J11.16 113.96,75.68 ; J11.16 114.69,76.41 ; SS6.1 95.22,13.09 ; SS6.1 92.44,10.32 ; SS6.1 89.66,13.09 ; SS6.1 92.44,15.87 ; 144.45,77.5 SW3.1 ; SW3.1 144.45,79.46 ; SW3.1 143.47,78.48 ; SW3.1 145.43,78.48 ; J4.11 145.09,26.15 ; J4.11 146.48,25.21 ; J4.11 143.71,25.21 ; v1(25.02,21.54) 25.02,21.02 C197.2 ; 16.44,10.32 SS5.1 ; SS5.1 19.22,13.09 ; SS5.1 16.44,15.87 ; SS5.1 13.66,13.09 ; SS8.1 138.32,64.83 ; SS8.1 138.32,60.47 ; SS8.1 136.15,62.65 ; SS8.1 140.5,62.65 ; 2.68,10.65 J14.26 ; J14.26 v1(5.23,10.65) ; J14.26 3.86,11.63 ; J14.26 3.86,9.67 ; 12.24,79.67 13.16,79.67 ; 13.16,79.67 13.16,78.15 ; 13.16,79.67 13.16,81.2 ; 13.16,79.67 14.09,79.67 ; 147.17,27.84 J19.11 ; J19.11 148.4,28.52 ; J19.11 148.4,27.16 ; 0.8,79.6 J21.3 ; J21.3 1.78,80.58 ; J21.3 1.78,78.62 ; J21.3 2.76,79.6 ; 143.71,9.71 J4.12 ; J4.12 146.48,9.71 ; J4.12 145.09,10.65 ; J12.10 131.33,78.5 ; J12.10 130.36,79.48 ; J12.10 129.38,78.5 ; J12.10 130.36,77.52 ; U10.7 29.58,68.96 C210.2 ; C196.2 v1(21.77,15.78) ; 134.43,10.61 J4.13 ; J4.13 135.49,9.54 ; J4.13 136.56,10.61 ; J4.10 136.56,25.21 ; J4.10 134.43,25.21 ; J4.10 135.49,25.99 ; C198.2 39.05,19.69 v1(39.18,19.82) ; 82.99,3.71 J30.6 ; J30.6 83.72,4.44 ; J30.6 84.45,3.71 ; J14.25 5.03,25.55 ; J14.25 3.86,24.57 ; J14.25 2.68,25.55 ; J14.25 3.86,26.53 ; 2.68,29.85 J15.26 ; J15.26 5.03,29.85 ; J15.26 3.86,30.83 ; J15.26 3.86,28.87 ; 145.42,74.55 SW2.3 ; SW2.3 147.38,74.55 ; SW2.3 146.4,75.53 ; SW2.3 146.4,73.57 ; 97.94,3.71 J26.4 ; J26.4 98.67,4.44 ; J26.4 99.4,3.71 ; 148.4,40.16 J19.10 ; J19.10 148.4,41.52 ; J19.10 147.17,40.84 ; J25.4 110.34,3.71 ; J25.4 109.62,4.44 ; J25.4 109.62,2.98 ; J25.4 108.89,3.71 ; J19.8 137.63,40.84 ; J19.8 136.4,41.52 ; J19.8 135.17,40.84 ; J19.8 136.4,40.16 ; 98.9,80.9 J33.2 98.32,81.47 ; 146.4,79.05 SW3.3 ; SW3.3 145.42,80.03 ; SW3.3 146.4,81.01 ; SW3.3 147.38,80.03 ; 114.69,78.15 J11.7 113.96,78.88 ; 114.12,60.47 SS7.1 ; SS7.1 114.12,64.83 ; SS7.1 116.3,62.65 ; J11.4 111.92,80.38 ; J11.4 110.46,80.38 ; J11.4 111.19,81.11 ; 100.92,11.83 J2.2 ; J2.2 101.62,12.53 ; J2.2 100.92,13.24 ; J2.2 100.21,12.53 ; J23.4 72.77,4.44 ; J23.4 73.5,3.71 ; J23.4 72.04,3.71 ; v1(31.24,21.54) 31.24,21.02 C190.2 ; 129.38,75.5 J12.4 ; J12.4 130.36,76.48 ; J12.4 131.33,75.5 ; J12.4 130.36,74.52 ; SW2.1 144.45,73.98 ; SW2.1 144.45,72.02 ; SW2.1 145.43,73 ; R212.2 36.03,18.94 v1(36.69,18.28) ; J15.25 5.03,44.75 ; J15.25 3.86,45.73 ; J15.25 2.68,44.75 ; J23.6 68.77,4.44 ; J23.6 68.04,3.71 ; J23.6 69.5,3.71
  BOTTOM w0.508: J19.9 134.75,27.84
  vias: v1(0.71,51.18) v1(0.71,47.37) v1(0.71,43.56) v1(0.71,39.75) v1(0.71,35.94) v1(0.71,32.13) v1(0.71,28.32) v1(0.71,24.51) v1(0.71,16.08) v1(0.71,15.08) v1(0.71,14.08) v1(0.71,13.08) v1(0.71,9.27) v1(0.71,5.46) v1(0.84,81.66) v1(0.84,77.85) v1(0.84,70.23) v1(0.84,66.42) v1(0.84,62.61) v1(0.84,58.8) v1(0.84,54.99) v1(1.29,1.67) v1(1.38,71.88) v1(2.22,89.02) v1(2.38,71.88) v1(2.62,22.3) v1(3.02,12.19) v1(3.38,71.88) v1(3.55,31.8) v1(3.55,23.85) v1(3.81,19.86) v1(3.89,58.8) v1(3.89,57.8) v1(4.04,50.98) v1(4.04,37.64) v1(4.05,36.25) v1(4.05,35.35) v1(4.05,34.25) v1(4.02,12.19) v1(4.38,71.88) v1(4.41,17.2) v1(4.41,15.93) v1(4.55,31.8) v1(4.55,23.85) v1(5.03,13.89) v1(5.01,0.84) v1(5.41,17.2) v1(5.41,15.93) v1(5.41,9.91) v1(5.54,39.4) v1(6.03,89.16) v1(6.53,44.07) v1(6.45,29.88) v1(6.45,28.88) v1(6.91,7.15) v1(7.11,11.48) v1(7.11,10.21) v1(7.53,44.07) v1(7.6,2.6) v1(7.8,49.69) v1(7.8,48.69) v1(7.82,40.77) v1(7.87,84) v1(7.87,82.73) v1(7.87,37.62) v1(8.08,41.61) v1(8.64,33.86) v1(8.6,3.6) v1(8.6,2.6) v1(8.82,0.84) v1(8.89,63.28) v1(8.97,37.62) v1(9.14,84) v1(9.14,82.73) v1(9.6,3.6) v1(9.6,2.6) v1(9.84,89.16) v1(9.75,25.79) v1(9.78,16.31) v1(10.13,36.25) v1(10.31,71.65) v1(10.41,84) v1(10.41,82.73) v1(10.53,44.07) v1(10.49,15.09) v1(10.6,3.6) v1(10.6,2.6) v1(10.92,25.79) v1(11.05,30.1) v1(10.97,22.38) v1(11.2,52.88) v1(11.53,44.07) v1(11.53,43.07) v1(11.6,3.6) v1(11.6,2.6) v1(11.68,84) v1(11.68,82.73) v1(11.77,22.38) v1(11.92,26.59) v1(11.92,25.79) v1(12.24,21.2) v1(12.37,28.12) v1(12.62,17.37) v1(12.65,16.33) v1(12.6,3.6) v1(12.6,2.6) v1(12.63,0.84) v1(12.88,38) v1(12.95,84) v1(12.95,82.73) v1(13.06,32.94) v1(13.54,45.24) v1(13.6,3.6) v1(13.6,2.6) v1(13.65,89.16) v1(13.94,43.48) v1(13.87,24.03) v1(13.97,36.02) v1(14,21.18) v1(14.22,84) v1(14.22,82.73) v1(14.22,32.94) v1(14.6,3.6) v1(14.6,2.6) v1(14.74,43.48) v1(14.73,42.6) v1(14.94,34.82) v1(15.14,24) v1(15.49,84) v1(15.49,82.73) v1(15.6,7.1) v1(15.6,6.1) v1(15.6,5.1) v1(15.6,3.6) v1(15.6,2.6) v1(15.73,42.6) v1(15.72,38.58) v1(15.9,33.93) v1(16,30.07) v1(15.98,29.06) v1(15.98,27.61) v1(16.44,53.1) v1(16.44,0.84) v1(16.6,3.6) v1(16.6,2.6) v1(16.76,85.27) v1(16.76,84) v1(16.76,82.73) v1(16.84,24.18) v1(16.94,62.33) v1(16.94,61.33) v1(16.94,60.33) v1(16.94,59.33) v1(16.94,57.33) v1(17.44,53.1) v1(17.46,89.16) v1(17.53,40.41) v1(17.6,3.6) v1(17.6,2.6) v1(17.75,76.86) v1(17.75,75.59) v1(18.03,85.27) v1(18.03,84) v1(18.03,82.73) v1(18.48,17.54) v1(18.59,36.68) v1(18.57,32.92) v1(18.6,3.6) v1(18.6,2.6) v1(19.08,75.59) v1(19.24,47.51) v1(19.24,46.41) v1(19.24,45.31) v1(19.24,44.21) v1(19.3,84) v1(19.3,82.73) v1(19.38,74.14) v1(19.38,72.98) v1(19.44,53.1) v1(19.44,52.1) v1(19.48,17.54) v1(19.6,3.6) v1(19.6,2.6) v1(19.73,11.47) v1(20,77.97) v1(20.25,0.84) v1(20.4,66.67) v1(20.57,84) v1(20.57,82.73) v1(20.57,81.46) v1(20.6,3.6) v1(20.6,2.6) v1(20.7,48.11) v1(20.73,12.47) v1(20.73,11.47) v1(20.83,80.21) v1(21.27,89.16) v1(21.33,74.32) v1(21.44,53.1) v1(21.44,52.1) v1(21.46,77.62) v1(21.48,20.54) v1(21.48,19.54) v1(21.48,14.02) v1(21.6,3.6) v1(21.6,2.6) v1(21.82,39.98) v1(21.82,36.14) v1(22.05,76.71) v1(22.06,44.46) v1(22.73,12.47) v1(22.81,85.04) v1(22.98,46.41) v1(22.98,45.31) v1(23.1,74.31) v1(23.44,30.44) v1(23.44,24.69) v1(23.55,41.68) v1(23.55,37.9) v1(23.52,7.11) v1(23.52,6.11) v1(23.52,5.11) v1(23.94,27.58) v1(23.94,26.58) v1(24.02,22.54) v1(24.1,76.33) v1(24.06,0.84) v1(24.33,24.69) v1(24.54,74.75) v1(24.52,7.11) v1(24.52,6.11) v1(24.65,70.6) v1(24.65,69.6) v1(24.65,68.6) v1(24.94,88.01) v1(24.94,87.01) v1(24.9,76.33) v1(24.99,29.57) v1(24.97,28.58) v1(24.97,27.58) v1(24.97,26.58) v1(25.33,24.69) v1(25.37,53.34) v1(25.52,73.43) v1(25.74,88.01) v1(25.65,70.6) v1(25.65,68.6) v1(25.67,59.43) v1(25.93,29.58) v1(26.04,12.47) v1(26.09,44.17) v1(26.09,40.39) v1(26.06,10.52) v1(26.39,79.27) v1(26.37,53.34) v1(26.54,88.01) v1(26.52,73.43) v1(26.47,34.11) v1(26.72,77.7) v1(26.65,70.6) v1(26.65,69.6) v1(26.67,58.43) v1(27.15,76.3) v1(27.33,10.52) v1(27.43,44.88) v1(27.43,41.76) v1(27.43,34.95) v1(27.67,59.43) v1(27.87,0.84) v1(28.45,25.35) v1(28.6,10.52) v1(28.73,76.3) v1(29.13,77.95) v1(29.09,17.01) v1(29.2,12.47) v1(29.31,87.99) v1(29.57,76.28) v1(29.77,47.65) v1(29.87,10.52) v1(30.05,81.33) v1(30.09,17.01) v1(30.73,45.06) v1(30.68,42.44) v1(30.84,87.6) v1(30.81,37.57) v1(31.11,70.49) v1(31.17,83.19) v1(31.39,82.35) v1(31.42,76.3) v1(31.68,0.84) v1(32.1,53.29) v1(32.09,17.01) v1(32.27,12.47) v1(32.97,53.29) v1(32.97,50.39) v1(33.31,85.01) v1(33.31,84.21) v1(33.31,83.41) v1(33.31,82.61) v1(33.71,47.68) v1(33.8,75.31) v1(33.83,53.29) v1(33.83,50.39) v1(33.88,45.03) v1(33.88,42.44) v1(33.88,37.57) v1(34.24,80.47) v1(34.32,89.26) v1(34.42,71.49) v1(34.75,47.68) v1(34.75,45.06) v1(34.75,42.44) v1(34.75,37.59) v1(34.75,28.09) v1(34.75,27.03) v1(34.9,4.17) v1(35.15,75.34) v1(35.42,71.49) v1(35.49,0.84) v1(35.79,47.65) v1(35.81,45.06) v1(35.84,42.44) v1(35.8,12.31) v1(35.8,11.31) v1(35.92,81.41) v1(35.99,88.44) v1(36.02,37.59) v1(35.97,34.25) v1(36.8,6.81) v1(36.98,28.09) v1(37.11,50.34) v1(37.19,74.8) v1(37.26,81.41) v1(37.26,77.85) v1(37.97,11.53) v1(38.19,74.8) v1(38.23,24.13) v1(38.25,32.25) v1(38.43,53.34) v1(38.43,50.34) v1(38.81,47.6) v1(38.81,45.03) v1(38.81,42.44) v1(38.81,37.59) v1(39.1,31.34) v1(39.19,74.8) v1(39.26,81.41) v1(39.3,0.84) v1(39.67,47.62) v1(39.67,45.03) v1(39.67,42.42) v1(39.67,37.59) v1(39.67,34.87) v1(40.19,74.8) v1(40.32,89.16) v1(40.74,79.3) v1(40.69,76.33) v1(41.43,47.62) v1(41.43,45.03) v1(41.43,37.59) v1(41.43,34.87) v1(41.53,53.64) v1(41.45,42.44) v1(43.11,0.84) v1(43.23,12.32) v1(43.23,11.32) v1(43.69,24.13) v1(44.13,89.16) v1(44.08,14.85) v1(44.25,50.34) v1(44.25,47.62) v1(44.25,42.44) v1(44.25,37.59) v1(44.27,45.03) v1(44.27,34.98) v1(44.96,24.13) v1(45.24,50.34) v1(45.24,47.65) v1(45.24,45.03) v1(45.24,42.44) v1(45.24,37.59) v1(45.59,27.58) v1(46,53.54) v1(46.2,50.34) v1(46.2,47.65) v1(46.18,45.09) v1(46.23,42.47) v1(46.94,37.59) v1(46.92,0.84) v1(47.94,89.16) v1(47.94,57.25) v1(48.94,57.25) v1(49.56,72.34) v1(49.86,31.32) v1(50.11,71.78) v1(50.6,37.59) v1(50.73,0.84) v1(50.75,89.29) v1(50.8,31.34) v1(53,75.16) v1(52.96,52.88) v1(53.2,89.29) v1(53.19,59.25) v1(53.33,24) v1(53.44,54.53) v1(53.54,87.99) v1(53.54,86.99) v1(53.54,85.99) v1(54.33,24) v1(54.28,17.02) v1(54.54,0.84) v1(55.24,24) v1(55.56,89.29) v1(55.6,27.58) v1(56.03,72.82) v1(56.24,24) v1(57.25,37.57) v1(57.35,31.34) v1(58.35,0.84) v1(59,14.38) v1(59.05,59.56) v1(59.29,81.82) v1(59.37,89.29) v1(59.73,16.35) v1(59.91,67.73) v1(60.29,81.82) v1(60.33,15.35) v1(60.73,16.35) v1(60.91,67.73) v1(60.91,40.01) v1(61.13,80.77) v1(61.29,81.82) v1(61.34,53.59) v1(61.91,67.73) v1(61.91,40.01) v1(61.96,29.86) v1(61.96,28.86) v1(61.96,27.86) v1(61.96,26.86) v1(62.2,65.61) v1(62.16,0.84) v1(62.29,81.82) v1(62.91,67.73) v1(63.09,16.33) v1(63.18,89.29) v1(63.29,81.82) v1(63.29,80.82) v1(63.54,35.41) v1(64.29,81.82) v1(64.46,38.03) v1(64.95,50.34) v1(64.95,46.99) v1(64.95,45.75) v1(64.94,16.35) v1(64.94,15.35) v1(65.07,42.6) v1(65.17,35.41) v1(65.17,30.92) v1(65.17,29.92) v1(65.17,28.92) v1(65.63,57.91) v1(65.68,38.03) v1(65.91,16.33) v1(65.97,0.84) v1(66.17,30.92) v1(66.17,29.92) v1(66.17,28.92) v1(66.4,35.41) v1(66.67,41.05) v1(66.99,89.29) v1(67.17,30.92) v1(67.17,29.92) v1(67.17,28.92) v1(67.49,16.35) v1(67.49,15.35) v1(67.49,14.35) v1(67.92,39.85) v1(68.78,37.03) v1(68.78,36.3) v1(68.78,35.41) v1(69.78,0.84) v1(69.99,72.72) v1(69.99,71.72) v1(70.66,51.92) v1(70.8,89.29) v1(70.89,49.28) v1(70.89,48.18) v1(70.91,46.99) v1(70.97,81.49) v1(70.97,75.14) v1(71.04,37.36) v1(70.97,20.21) v1(71.25,50.83) v1(71.27,61.39) v1(71.42,45.77) v1(71.41,44.7) v1(71.4,43.64) v1(71.41,42.44) v1(71.74,89.29) v1(71.97,20.21) v1(72.73,89.29) v1(72.69,62.12) v1(72.69,61.12) v1(73.08,57.89) v1(73.07,16.27) v1(73.59,0.84) v1(73.97,20.21) v1(74.22,45.2) v1(74.45,41.5) v1(74.43,26) v1(74.61,89.29) v1(75.03,37.36) v1(74.97,20.21) v1(75.51,67.11) v1(75.64,72.09) v1(75.67,65.18) v1(76.44,20.21) v1(76.63,66.27) v1(76.72,17.78) v1(77.4,0.84) v1(77.72,17.78) v1(78.16,45.19) v1(78.19,29.86) v1(78.19,28.86) v1(78.42,89.29) v1(78.51,41.48) v1(78.48,37.36) v1(78.72,17.78) v1(79.07,81.77) v1(79.11,13.64) v1(79.11,12.64) v1(79.11,10.64) v1(79.11,9.64) v1(79.11,8.64) v1(79.11,7.64) v1(79.33,33.19) v1(79.53,67.41) v1(79.45,36.55) v1(79.72,17.78) v1(79.81,35.46) v1(80.07,81.77) v1(81.07,81.77) v1(81.21,0.84) v1(81.28,62.18) v1(81.32,17.78) v1(81.37,35.43) v1(81.4,30.92) v1(81.4,29.92) v1(81.4,28.92) v1(81.41,8.91) v1(81.69,60.5) v1(81.89,52.35) v1(81.94,48.59) v1(81.94,45.59) v1(82.07,81.77) v1(82.09,41.43) v1(82.23,89.29) v1(82.4,30.92) v1(82.4,29.92) v1(82.4,28.92) v1(82.61,35.43) v1(82.85,69.34) v1(83.07,81.77) v1(83.1,17.78) v1(83.19,10.91) v1(83.19,9.91) v1(83.19,8.91) v1(83.4,30.92) v1(83.4,29.92) v1(83.4,28.92) v1(84.07,81.77) v1(84.12,69.34) v1(84.87,17.78) v1(85.01,41.48) v1(85.01,37.03) v1(84.96,10.91) v1(84.96,9.91) v1(84.96,8.91) v1(85.02,0.84) v1(85.07,81.77) v1(85.07,80.77) v1(85.19,35.45) v1(85.62,33.2) v1(86.04,89.29) v1(86.01,37.03) v1(86.21,66.34) v1(86.74,10.91) v1(86.74,9.91) v1(86.74,8.91) v1(87.01,37.03) v1(87.2,20.19) v1(87.5,66.34) v1(88.01,37.03) v1(88.2,20.19) v1(88.16,17.78) v1(88.81,22.45) v1(88.83,0.84) v1(89.01,37.03) v1(89.16,17.78) v1(89.85,89.29) v1(90.27,71.55) v1(90.86,69.1) v1(90.86,68.21) v1(91.11,52.81) v1(91.11,51.81) v1(91.11,50.81) v1(91.18,21.06) v1(91.2,20.19) v1(91.72,25.98) v1(91.86,69.1) v1(91.86,68.21) v1(91.97,74.42) v1(92.23,36.55) v1(92.18,21.06) v1(92.49,62.41) v1(92.48,61.57) v1(92.58,82.3) v1(92.56,79.81) v1(92.56,77.57) v1(92.56,39.83) v1(92.64,0.84) v1(92.86,70.1) v1(92.86,69.1) v1(93.29,62.41) v1(93.66,89.29) v1(94.23,32.51) v1(94.39,48.59) v1(94.36,46.61) v1(94.36,41.38) v1(94.74,40.11) v1(94.74,38.84) v1(94.72,27) v1(95.12,33.66) v1(95.72,27) v1(96.01,38.84) v1(95.96,36.53) v1(96.45,0.84) v1(96.72,27) v1(97.01,52.84) v1(97.28,38.84) v1(97.38,69.9) v1(97.47,89.29) v1(97.71,29.08) v1(97.72,27) v1(98.01,52.84) v1(98.07,83.01) v1(98.32,38.84) v1(99.01,52.84) v1(99.65,28.66) v1(100.25,63.02) v1(100.26,0.84) v1(100.94,37.87) v1(100.97,48.83) v1(101.28,89.29) v1(101.32,21.07) v1(101.97,48.83) v1(102.16,68.68) v1(102.32,21.07) v1(102.36,70.05) v1(102.59,84) v1(102.59,83) v1(102.59,82) v1(102.59,81) v1(102.59,80) v1(102.58,43.56) v1(102.58,42.29) v1(102.59,38.94) v1(103.23,19.57) v1(103.38,78.13) v1(103.43,63.78) v1(103.4,58.57) v1(103.59,83) v1(103.59,82) v1(103.59,81) v1(103.59,80) v1(103.68,69.39) v1(104.07,0.84) v1(104.29,14.45) v1(104.8,73.18) v1(105.09,89.29) v1(105.27,50.6) v1(105.77,17.35) v1(107.29,40.86) v1(107.29,39.86) v1(107.31,38.33) v1(107.34,25.98) v1(107.75,70.08) v1(107.88,0.84) v1(108.13,25.25) v1(108.2,36.17) v1(108.3,73.85) v1(108.29,40.86) v1(108.29,39.86) v1(108.9,89.16) v1(108.86,14.98) v1(108.86,13.98) v1(108.86,12.98) v1(109.17,49.56) v1(109.2,47.05) v1(109.3,73.85) v1(109.3,72.85) v1(109.77,20.78) v1(109.77,19.78) v1(109.86,14.98) v1(109.86,13.98) v1(109.86,12.98) v1(109.86,11.98) v1(110.2,47.05) v1(110.3,73.85) v1(110.3,72.85) v1(110.3,71.85) v1(110.38,86.74) v1(110.38,85.74) v1(110.38,84.74) v1(110.38,83.74) v1(110.95,40.79) v1(110.97,30.16) v1(110.97,29.16) v1(110.97,28.16) v1(110.97,27.16) v1(111.3,73.85) v1(111.3,72.85) v1(111.3,70.85) v1(111.38,86.74) v1(111.38,85.74) v1(111.38,84.74) v1(111.38,83.74) v1(111.51,19.76) v1(111.71,49.56) v1(111.69,0.84) v1(112.38,85.74) v1(112.38,84.74) v1(112.38,83.74) v1(112.71,89.16) v1(112.77,19.22) v1(112.77,18.22) v1(112.77,16.22) v1(113.01,67.17) v1(113.01,66.38) v1(113.13,71.12) v1(113.13,49.56) v1(113.77,19.22) v1(113.77,18.22) v1(113.77,16.22) v1(114.17,31.11) v1(114.33,52.91) v1(114.58,13.26) v1(114.67,86.74) v1(114.67,85.74) v1(114.85,66.38) v1(114.81,34.75) v1(114.81,32.56) v1(115.5,0.84) v1(115.58,13.26) v1(115.67,86.74) v1(115.72,67.69) v1(115.81,34.75) v1(115.81,33.66) v1(115.81,32.56) v1(115.81,31.56) v1(115.81,30.56) v1(115.93,84.76) v1(116.38,26.95) v1(116.52,89.16) v1(116.6,56.24) v1(116.74,50.42) v1(116.81,34.75) v1(116.81,33.66) v1(116.81,32.56) v1(116.81,31.56) v1(116.81,30.56) v1(116.92,84.72) v1(116.92,83.72) v1(117.09,37.43) v1(117.25,16.24) v1(117.25,15.24) v1(117.81,34.75) v1(117.81,33.66) v1(117.81,32.56) v1(117.78,26.64) v1(117.86,67.67) v1(118.08,41.99) v1(118.09,37.43) v1(118.85,39.67) v1(119.09,37.43) v1(119.2,53.42) v1(119.25,13.24) v1(119.41,26.64) v1(119.51,66.19) v1(119.56,43.21) v1(119.71,49) v1(120.07,54.97) v1(120.09,37.43) v1(120.08,16.24) v1(120.08,15.24) v1(120.22,59.61) v1(120.33,89.16) v1(120.33,70.18) v1(120.33,69.18) v1(120.33,68.18) v1(120.33,67.18) v1(120.33,66.18) v1(120.33,20.06) v1(120.25,13.24) v1(120.9,41.7) v1(120.9,40.7) v1(120.9,39.7) v1(121.01,26.64) v1(121.09,37.43) v1(121.54,23.16) v1(121.54,22.33) v1(121.72,50.9) v1(121.77,59.26) v1(121.79,56.01) v1(121.77,53.75) v1(122.15,64.03) v1(122.17,61.82) v1(122.65,27.19) v1(123.32,49.3) v1(123.65,27.19) v1(123.99,25.15) v1(124.14,89.16) v1(124.64,17.26) v1(124.64,14.26) v1(124.71,67.01) v1(124.69,64.36) v1(124.65,27.19) v1(125.64,17.26) v1(125.64,14.26) v1(125.68,32.61) v1(125.68,31.37) v1(125.65,30.25) v1(125.65,28.25) v1(126.62,17.24) v1(126.64,16.26) v1(126.64,15.26) v1(126.64,14.26) v1(126.85,67.03) v1(126.87,65.51) v1(127.59,58.99) v1(127.59,57.99) v1(127.64,16.26) v1(127.64,15.26) v1(127.81,27.95) v1(127.95,89.16) v1(128.28,41.77) v1(128.59,57.99) v1(128.63,25.11) v1(129.28,33.78) v1(129.39,49.47) v1(129.39,42.47) v1(129.44,27.97) v1(129.59,57.99) v1(129.69,32.21) v1(130.28,25.32) v1(130.51,42.27) v1(131.42,32.51) v1(131.76,89.16) v1(131.75,0.74) v1(132.26,27.97) v1(132.28,26.24) v1(132.54,49.99) v1(132.54,41.99) v1(132.82,33.86) v1(133.54,49.99) v1(133.54,48.99) v1(133.6,34.87) v1(133.85,87.74) v1(133.85,86.74) v1(133.85,85.74) v1(134.54,49.99) v1(134.55,0.74) v1(134.85,86.74) v1(134.98,69.62) v1(135.54,42.99) v1(135.54,41.99) v1(135.57,89.16) v1(135.85,86.74) v1(136.35,38.86) v1(136.54,42.99) v1(136.54,41.99) v1(136.75,70.89) v1(137.02,4.06) v1(137.5,14.36) v1(138.28,31.78) v1(138.36,0.84) v1(138.94,32.89) v1(139.02,16.24) v1(139.38,89.16) v1(139.94,32.89) v1(140.08,30.73) v1(140.67,27.51) v1(140.67,26.51) v1(140.8,15.38) v1(140.94,32.89) v1(141.12,24.35) v1(141.22,30.73) v1(141.25,21.36) v1(141.17,20.24) v1(141.67,26.51) v1(141.73,15.42) v1(141.94,32.89) v1(141.88,27.89) v1(142.17,0.84) v1(142.37,30.73) v1(142.94,32.89) v1(142.88,27.89) v1(143.19,89.16) v1(143.21,9.45) v1(143.38,30.73) v1(143.94,32.89) v1(144.15,27.89) v1(144.53,30.73) v1(144.53,18.59) v1(144.65,39.24) v1(144.65,38.35) v1(144.65,37.59) v1(144.65,36.7) v1(144.65,35.81) v1(144.65,34.92) v1(144.68,21.13) v1(144.94,32.89) v1(145.29,39.75) v1(145.54,30.73) v1(145.58,13.24) v1(145.92,36.7) v1(145.94,35.89) v1(145.94,34.89) v1(145.94,33.89) v1(145.94,32.89) v1(146.18,30.73) v1(146.3,39.75) v1(146.25,18.59) v1(146.56,27.1) v1(146.74,19.81) v1(147,89.16) v1(148.08,39.75) v1(148.21,30.86) v1(148.97,39.75) v1(148.97,36.32) v1(148.97,35.31) v1(148.97,34.42) v1(148.97,32.77) v1(148.97,31.11) v1(149.16,82.94) v1(149.16,79.13) v1(149.16,75.32) v1(149.16,71.51) v1(149.16,67.7) v1(149.16,63.89) v1(149.16,60.08) v1(149.16,56.27) v1(149.16,52.46) v1(149.16,48.65) v1(149.16,44.84) v1(149.16,29.6) v1(149.16,2.93) v1(149.29,25.79) v1(149.29,21.98) v1(149.29,18.17) v1(149.29,14.36) v1(149.29,10.55) v1(149.29,6.74) v2(0.91,60.98) v2(0.91,59.98) v2(3.2,56.25) v2(3.7,68.4) v2(4.2,56.25) v2(4.7,68.4) v2(4.7,65.9) v2(4.7,64.9) v2(6.2,71.78) v2(7.14,65.91) v2(7.2,71.78) v2(7.41,67.43) v2(8.2,71.78) v2(8.56,57.12) v2(9.56,57.66) v2(9.56,56.66) v2(10.56,57.66) v2(11.94,66.01) v2(11.94,65.01) v2(12.25,76.98) v2(13.25,76.98) v2(14.25,76.98) v2(15.25,76.98) v2(15.18,69.22) v2(15.18,68.22) v2(16.25,76.98) v2(16.18,74.98) v2(16.18,73.98) v2(16.18,72.98) v2(16.18,71.98) v2(16.18,70.98) v2(16.18,69.24)
